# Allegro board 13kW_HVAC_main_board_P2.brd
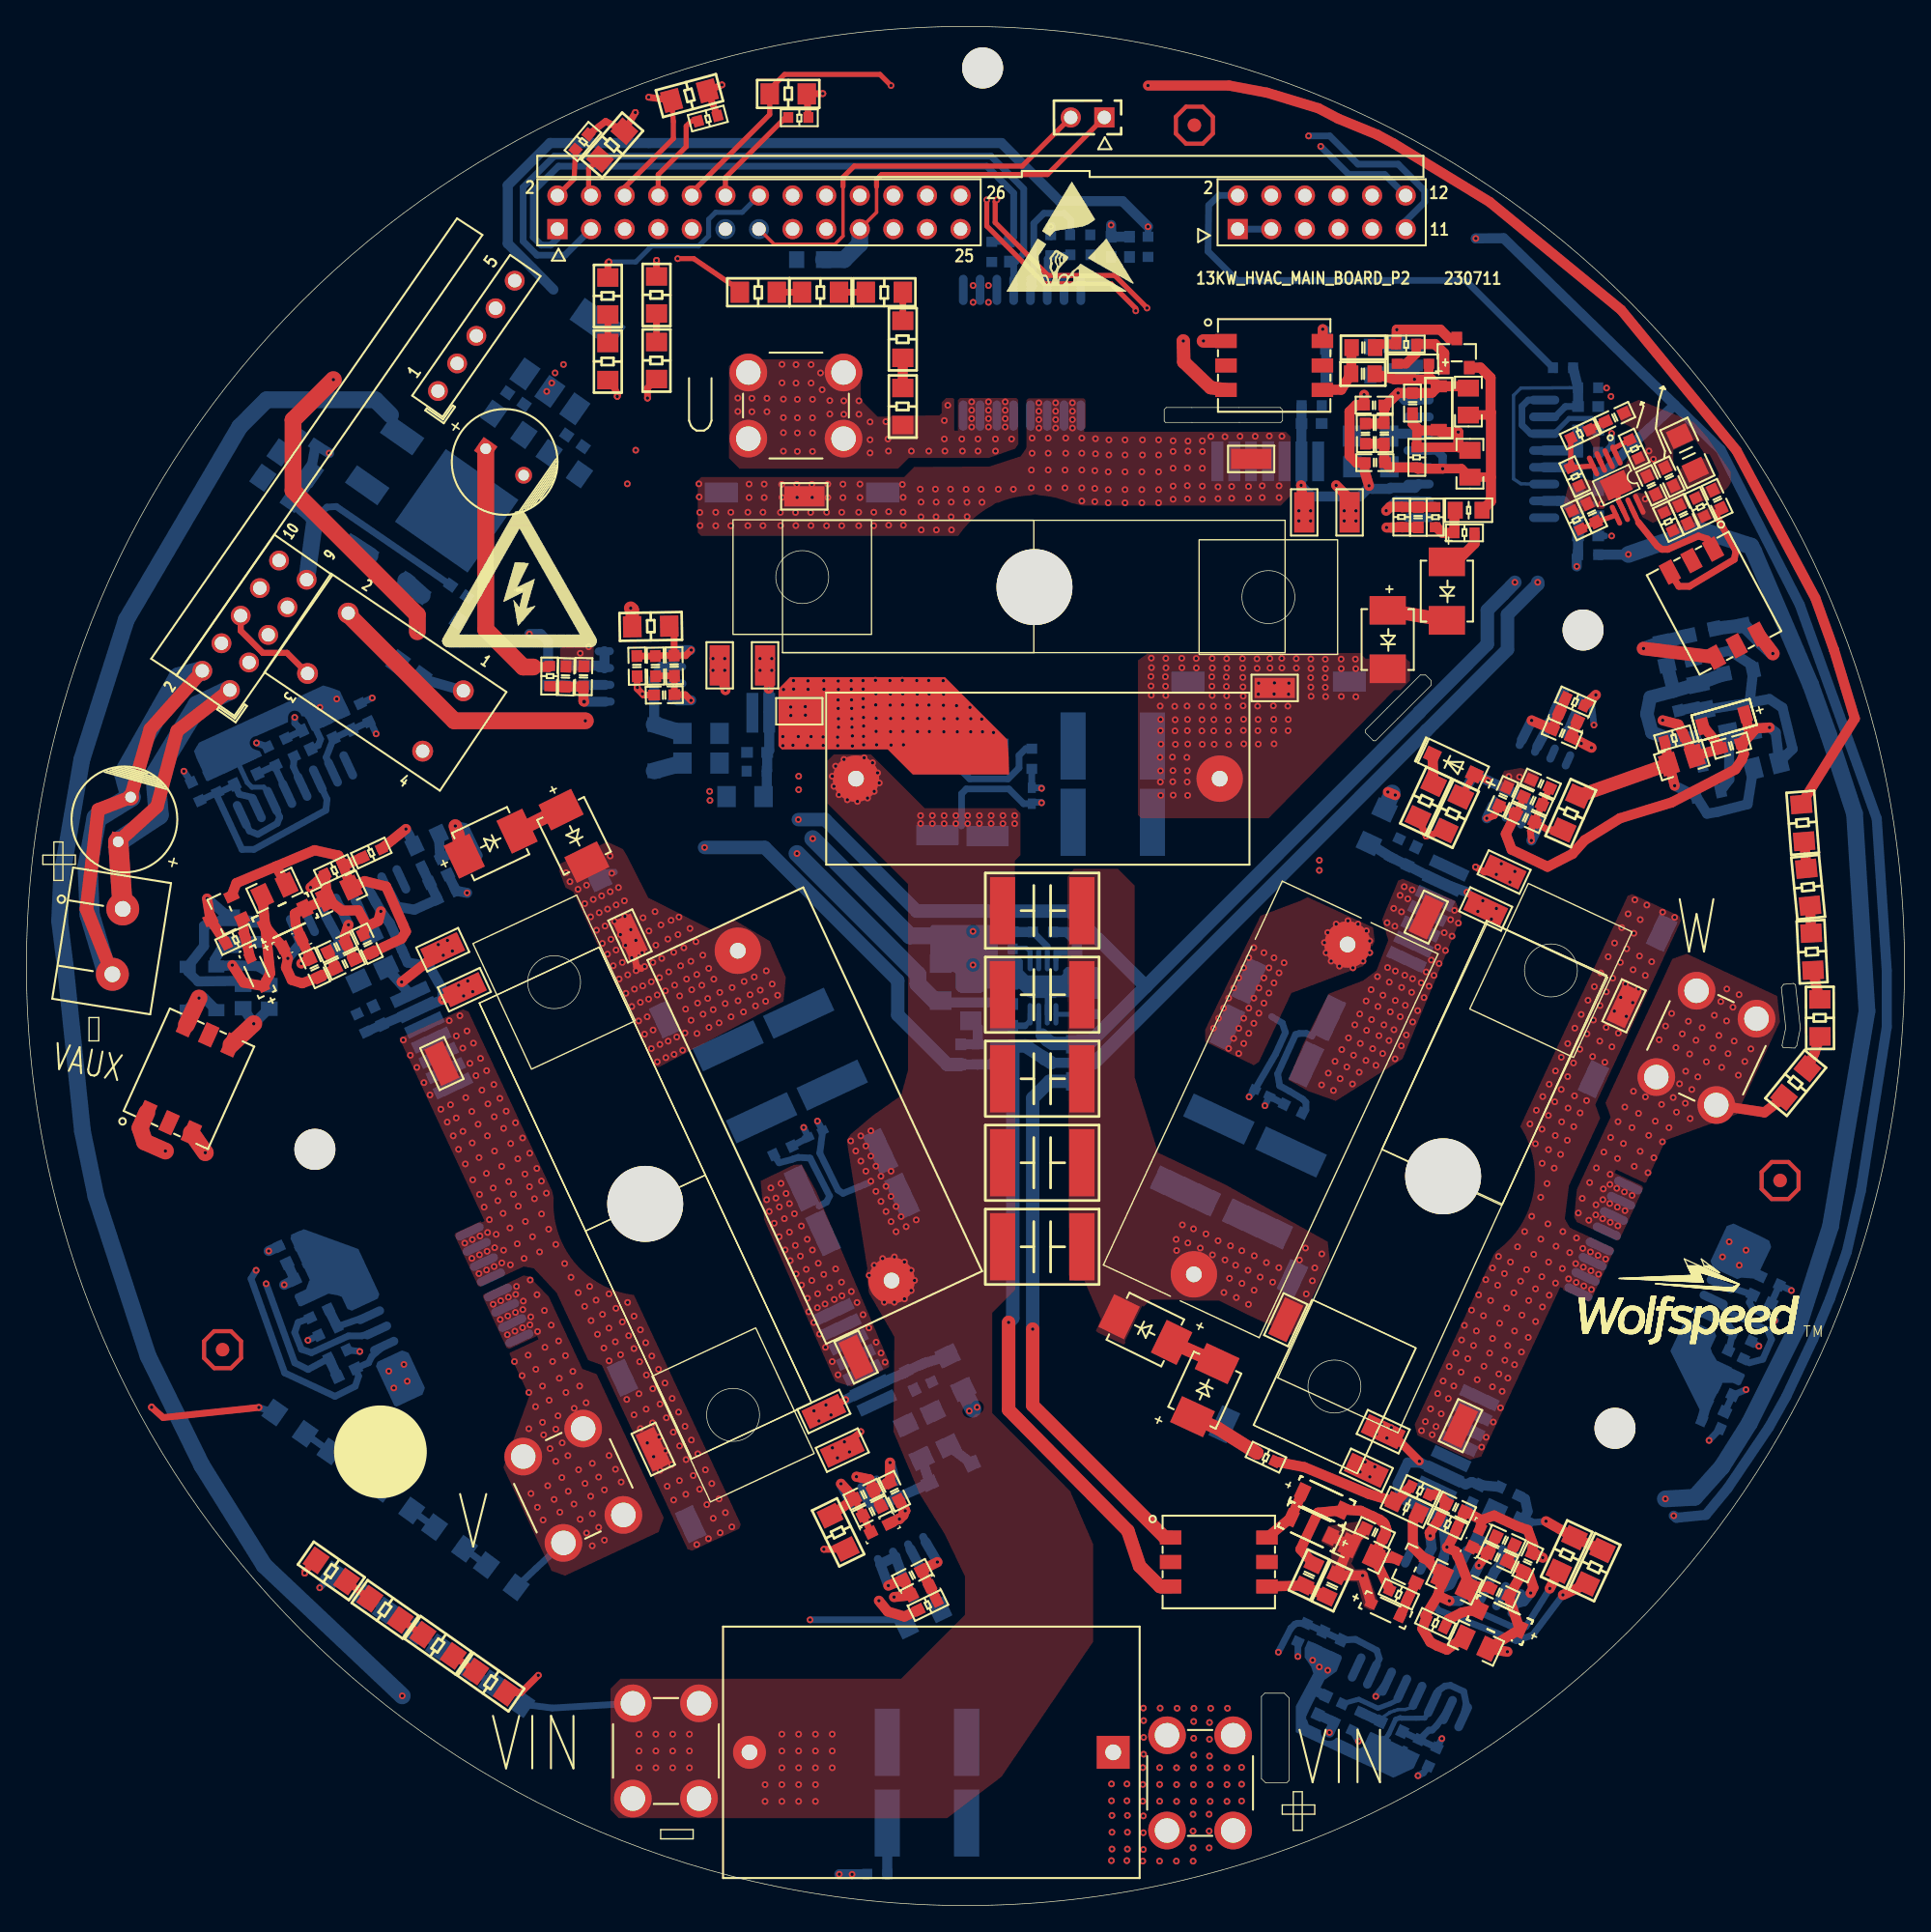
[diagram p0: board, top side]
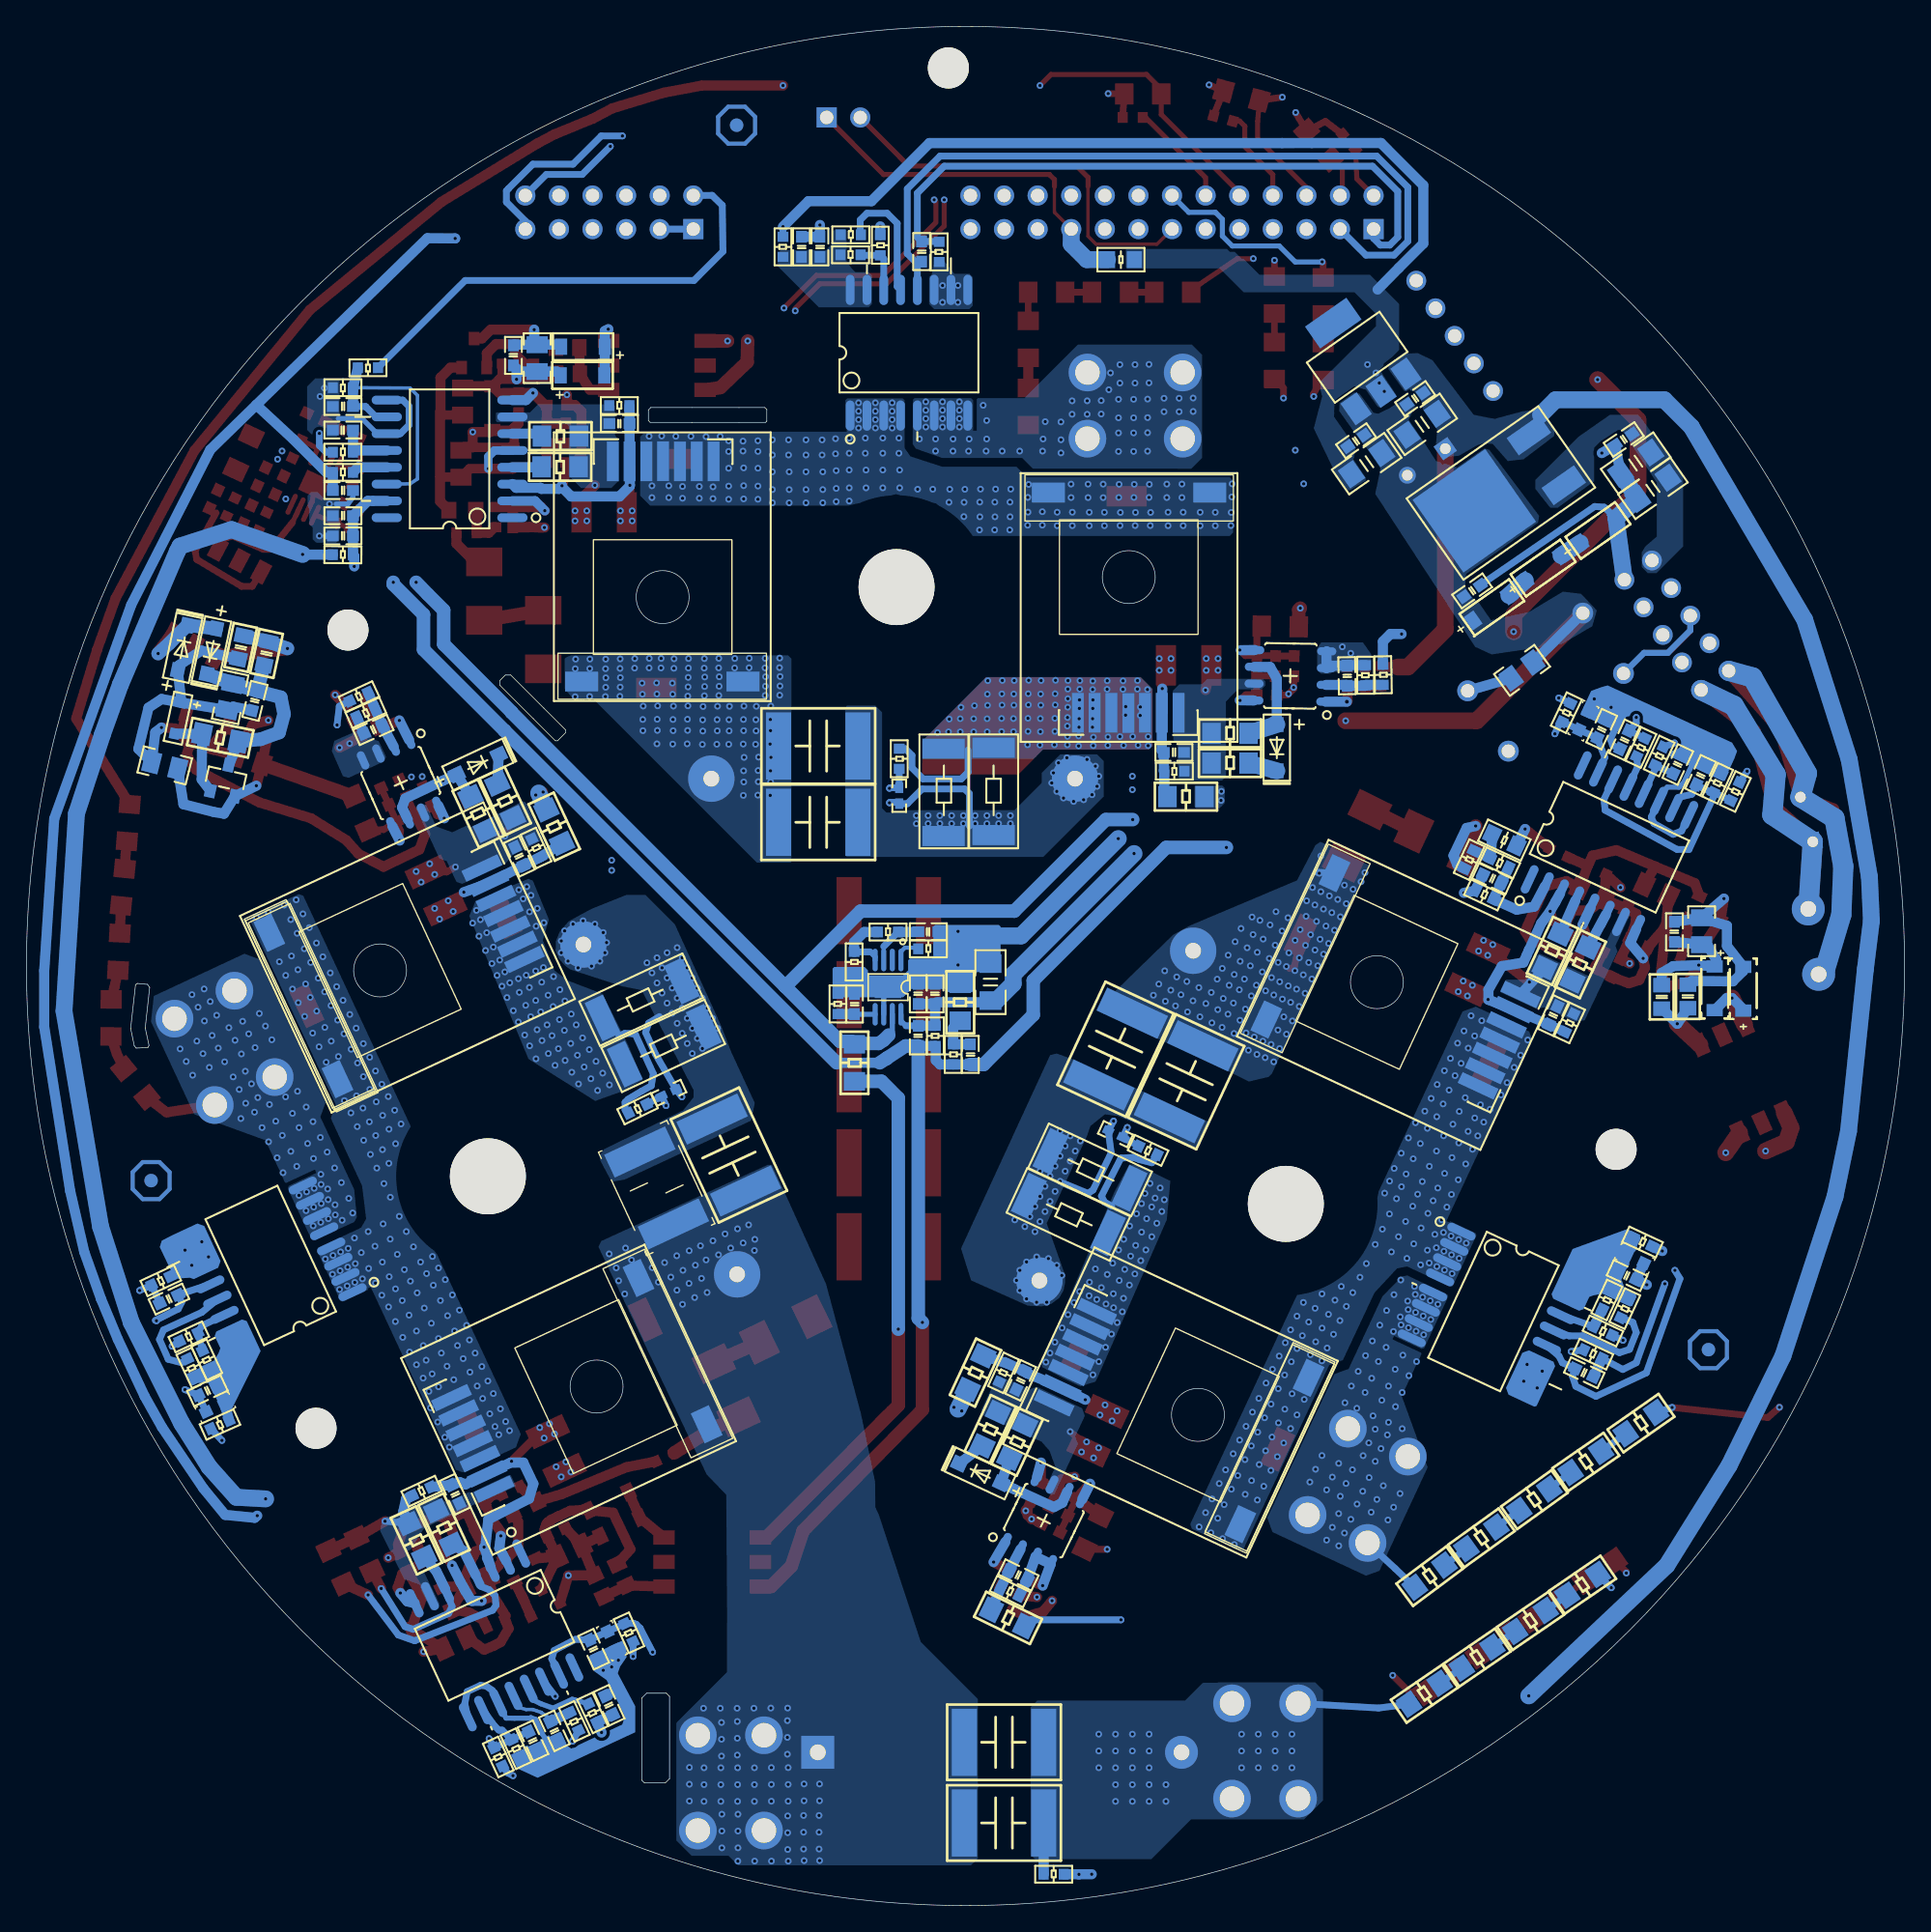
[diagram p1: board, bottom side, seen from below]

Outline 142 x 142 mm; copper layers: TOP, VCC02, GND03, PWM04, I_SAMPLING05, BOTTOM. Coordinates in mm from the lower left corner of the outline.
Outline path: circle c39.89,69.78 r2 ; circle c53.43,37.08 r2 ; circle c58.66,100.39 r2 ; circle c71,71 r71 ; circle c93.9,98.88 r2 ; circle c98.89,39.22 r2 ; circle c115.26,70.67 r2 ; 86.02,113.05 86.02,112.17 86.12,112.08 91.7,112.08 91.7,112.08 94.84,112.08 94.98,112.22 94.98,113.02 94.79,113.2 86.17,113.2 86.02,113.05 ; 93.38,15.8 93.38,9.59 93.7,9.27 95.28,9.27 95.47,9.46 95.47,15.68 95.1,16.05 93.62,16.05 93.38,15.8 ; 101.24,88.84 101.24,88.63 101.84,88.02 102.01,88.02 106.2,92.22 106.2,92.57 105.79,92.99 105.38,92.99 101.24,88.84 ; 132.69,69.38 132.85,69.61 133.61,69.68 133.75,69.59 134.12,66.29 133.85,64.98 133.7,64.8 132.82,64.84 132.74,65 133.02,66.32 132.69,69.38

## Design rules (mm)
net group 40MIL: nets IPH_U+ IPH_V+ IPH_W+

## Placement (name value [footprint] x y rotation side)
C1  1nF  [C0603]  97.16 112 180 bottom
C2  1nF  [C0603]  109.59 31.09 65 bottom
C3  1nF  [C0603]  26.56 67.26 295 bottom
C4  1nF  [C0603]  66.83 39.69 115 bottom
C5  1nF  [C0603]  104.74 79.29 245 bottom
C6  1nF  [C0603]  55.24 87.14 0 bottom
C7  5uF  [CAPFILM_31_5X18_5MM]  68.42 11.58 180 top
C8  2uF  [CAPFILM_31_5X12_5MM]  59.6 59.69 295 top
C9  2uF  [CAPFILM_31_5X12_5MM]  94.08 60.16 65 top
C10  2uF  [CAPFILM_31_5X12_5MM]  76.47 85.16 180 top
C11  0.22U  [C2220]  54.32 62.25 295 bottom
C12  0.22U  [C2220]  94.35 54.22 65 bottom
C13  0.22U  [C2220]  82.13 87.63 180 bottom
C14  NA  [0402]  59.66 58.3 25 bottom
C15  NA  [0402]  76.01 83.87 270 bottom
C16  NA  [0402]  93.43 61.42 155 bottom
C17  GRT21BR61H475KE13L  [C0603]  40.77 92.86 268 top
C18  0.1uF  [C0603]  42.13 92.87 269 top
C19  4.7uF  [C0603]  20.4 48.87 205 bottom
C20  4.7uF  [C0603]  83.4 125.34 90 bottom
C21  0.1uF  [C0603]  20.99 47.61 205 bottom
C22  0.1uF  [C0603]  82.01 125.34 90 bottom
C23  330pF  [C0603]  24.21 40.27 205 bottom
C24  330pF  [C0603]  74.32 124.99 90 bottom
C25  100pF  [C0603]  42.15 92.94 89 bottom
C26  1uF  [C0603]  46.16 93.66 271 top
C27  0.1uF  [C0603]  48.98 93.69 271 top
C28  2.2uF  [C0603]  47.56 93.66 271 top
C29  1uF  [C0603]  48.22 91.49 1 top
C30  100pF  [C0603]  118.07 113.28 0 bottom
C31  100pF  [C0603]  118.07 106.93 0 bottom
C32  4.7uF  [C0603]  127.73 37.63 335 bottom
C33  0.1uF  [C0603]  128.32 38.89 335 bottom
C34  GRT21BR61H475KE13L  [C0603]  67.62 23.79 26 top
C35  25V 220uF  [ECAP_D8P3_5]  7.41 82.08 74.5 top
C36  0.1uF  [C0603]  66.97 24.98 27 top
C37  1uF  [C0603]  101.95 109.04 180 top
C38  4.7uF  [C0603]  118.07 103.5 359.9 bottom
C39  330pF  [C0603]  131.23 45.83 335 bottom
C40  0.1uF  [C0603]  118.07 105.02 0 bottom
C41  25V 220uF  [ECAP_D8P3_5]  36.16 109.09 325 top
C42  10UF/25V  [C1206]  20.32 109 325 bottom
C43  2.2uF  [C0603]  102.66 111.24 90.3 top
C44  0.1uF  [C0603]  101.23 111.23 90.4 top
C45  1uF  [C0603]  101.9 113.39 0 top
C46  10UF/25V  [C1206]  19.02 107.09 325 bottom
C47  0.1uF  [C0603]  21.23 110.79 326 bottom
C48  100pF  [C0603]  67 24.98 206 bottom
C49  1uF  [C0603]  64.53 28.52 26 top
C50  0.1uF  [C0603]  63.31 31.07 26 top
C51  2.2uF  [C0603]  63.94 29.79 26 top
C52  1uF  [C0603]  65.63 31.31 116 top
C53  1uF  [C0603]  124.22 107.98 295 top
C54  47pF  [C0603]  105.23 104.91 270 top
C55  GRT21BR61H475KE13L  [C0603]  116.6 89.85 156 top
C56  0.1uF  [C0603]  116.1 88.58 157 top
C57  GRT21BR61H475KE13L  [0805_HV]  125.16 86.56 17.5 top
C58  3.3nF  [C0805]  123.85 94.62 102.2 bottom
C59  GRT21BR61H475KE13L  [0805_HV]  126.6 91.33 281.9 bottom
C60  1uF  [C0603]  125.3 105.12 295 top
C61  0.1uF  [C0603]  124.73 91.04 283.9 bottom
C62  GRT21BR61H475KE13L  [0805_HV]  131.55 86.16 14 bottom
C63  3.3nF  [C0805]  125.8 95.08 282 bottom
C64  10uF/35V  [C1206]  125.58 109.78 115 top
C65  1uF  [C0603]  120.1 112.46 25 top
C66  100pF  [C0603]  118.35 105.24 115 top
C67  GRT21BR61H475KE13L  [C0603]  128.89 87.65 15.8 top
C68  100pF  [C0603]  115.78 88.85 336 bottom
C69  1uF  [C0603]  127.83 106.28 115 top
C70  1uF  [C0603]  114.49 84.77 156 top
C71  0.1uF  [C0603]  113.32 82.2 156 top
C72  2.2uF  [C0603]  113.89 83.5 156 top
C73  1uF  [C0603]  111.65 83.82 246 top
C74  100pF  [C0603]  15.42 85.41 115 bottom
C75  100pF  [C0603]  21.17 88.1 115 bottom
C76  GRT21BR61H475KE13L  [0805_HV]  109.14 108.96 90 top
C77  3.3nF  [C0805]  101.08 117.73 180 top
C78  GRT21BR61H475KE13L  [0805_HV]  103.39 116.94 270 bottom
C79  1uF  [C0603]  25.77 72.69 115 top
C80  0.1uF  [C0603]  105.18 117.14 270 bottom
C81  GRT21BR61H475KE13L  [0805_HV]  109.02 113.65 90 top
C82  4.7uF  [C0603]  24.28 89.54 114.9 bottom
C83  3.3nF  [C0805]  101.05 115.75 0 top
C84  0.1uF  [C0603]  22.9 88.9 115 bottom
C85  0.1uF  [C0603]  24.08 71.13 205.4 top
C86  2.2uF  [C0603]  23.47 72.43 205.3 top
C87  GRT21BR61H475KE13L  [C0603]  104.8 113.54 90 top
C88  1uF  [C0603]  21.79 70.85 295 top
C89  100pF  [C0603]  103.7 12.45 245 bottom
C90  100pF  [C0603]  97.95 15.13 245 bottom
C91  1uF  [C0603]  73.3 68.89 270 bottom
C92  GRT21BR61H475KE13L  [0805_HV]  23.63 76.49 205 top
C93  3.3nF  [C0805]  16.38 68.7 270 bottom
C94  1uF  [C0603]  109.59 27.78 65 top
C95  GRT21BR61H475KE13L  [0805_HV]  15.35 73.63 270 bottom
C96  4.7uF  [C0603]  97.74 20.01 244.9 bottom
C97  0.1uF  [C0603]  17.4 73.58 270 bottom
C98  GRT21BR61H475KE13L  [0805_HV]  18.75 76.72 205 top
C99  0.1uF  [C0603]  99.12 19.37 245 bottom
C100  0.1uF  [C0603]  111.83 27.6 335.4 top
C101  2.2uF  [C0603]  111.23 26.31 335.3 top
C102  3.3nF  [C0805]  18.36 68.66 90 bottom
C103  47pF  [C0603]  31.17 77.6 25 bottom
C104  1uF  [C0603]  74.57 65.72 270 bottom
C105  GRT21BR61H475KE13L  [C0603]  20.09 72.73 205 top
C106  1uF  [C0603]  113.51 25.95 245 top
C107  10uF/35V  [C1206]  69.11 69.78 90 bottom
C108  100pF  [C0603]  79.4 68.13 90 bottom
C109  1uF  [C0603]  73.81 73.59 180 bottom
C110  1uF  [C0603]  70.63 64.32 90 bottom
C111  GRT21BR61H475KE13L  [0805_HV]  107.96 24.44 335 top
C112  3.3nF  [C0805]  96.97 24.99 245 top
C113  GRT21BR61H475KE13L  [0805_HV]  100.95 26.79 155 top
C114  0.1uF  [C0603]  101.94 28.19 155 top
C115  GRT21BR61H475KE13L  [0805_HV]  109.6 19.84 335 top
C116  3.3nF  [C0805]  98.71 24.15 65 top
C117  47pF  [C0603]  108.07 30.11 335 top
C118  GRT21BR61H475KE13L  [C0603]  111.38 23.67 335 top
C119  0.1uF  [C0603]  122.87 107.32 295 top
C120  0.1uF  [C0603]  74.57 68.89 270 bottom
C121  100pF  [C0603]  118.07 111.5 180 bottom
C122  100pF  [C0603]  17.14 86.22 295 bottom
C123  100pF  [C0603]  102.09 13.2 65 bottom
C124  10UF/25V  [C1206]  36.47 111.93 325 bottom
C125  10UF/25V  [C1206]  40.67 108.96 145 bottom
C126  0.1uF  [C0603]  41.47 110.69 145 bottom
C127  0.1uF  [C0603]  37 113.87 325 bottom
C128  GRT21BR61H475KE13L  [0805_HV]  28.92 93.34 144 bottom
C129  1uF  [C0603]  32.69 99.34 325 bottom
C130  0.47uF  [C2220]  76.8 56.13 180 top
C131  0.47uF  [C2220]  76.8 75.18 180 top
C133  0.22U  [C2220]  68.09 6.24 180 bottom
C134  0.22U  [C2220]  82.13 81.86 180 bottom
C135  0.47uF  [C2220]  76.8 68.83 180 top
C136  0.47uF  [C2220]  76.8 49.78 180 top
C137  0.47uF  [C2220]  76.8 62.48 180 top
C138  0.22U  [C2220]  88.89 56.71 65 bottom
C139  0.22U  [C2220]  59.65 64.71 295 bottom
C140  0.22U  [C2220]  68.09 12.34 180 bottom
CN1  -  [CON_5MM_2X1]  6.89 72.84 261 top
CN2  con_2mm54_5x2  [CON_2MM54_5X2]  17.24 96.75 55.2 top
CN3  con_2mm54_5x1  [CON_2MM54_5X1]  34.02 118.62 55.2 top
CON1  CON  [CON4_500X720-800X800]  88.74 9.27 0 top
CON2  CON  [CON4_500X720-800X800]  48.35 11.68 0 top
CON3  CON  [CON4_500X720-800X800]  41.35 31.72 25 top
CON4  CON  [CON4_500X720-800X800]  127.02 64.81 335 top
CON5  CON  [CON4_500X720-800X800]  58.18 113.35 270 top
D1  SL14PL-TP  [SOD-123]  107.88 86.22 155 bottom
D1_2  SL14PL-TP  [SOD-123]  107.89 86.21 155 top
D2  SL14PL-TP  [SOD-123]  69.89 32.66 25 bottom
D3  SL14PL-TP  [SOD-123]  47.46 87.5 270 bottom
D4  MURS160T3G  [SMB]  107.39 99.33 90 top
D5  MURS160T3G  [SMB]  102.92 95.67 90 top
D6  PMEG6010CEGWJ  [SOD-123]  128.01 94.78 282 bottom
D7  18.51V  [SOD323F]  130.54 89.73 282.2 bottom
D8  PMEG6010CEGWJ  [SOD-123]  130.19 95.04 102 bottom
D9  3V  [SMDSOD123]  128.36 89.58 15.8 top
D10  PMEG6010CEGWJ  [SMDSOD123]  99.92 117.8 180 bottom
D11  18.51V  [SOD323F]  104.83 116.51 180 top
D12  PMEG6010CEGWJ  [SMDSOD123]  99.96 115.63 0 bottom
D13  3V  [SMDSOD123]  106.78 113.16 90 top
D14  MURS160T3G  [SMB]  35.1 80.25 205.3 top
D15  MURS160T3G  [SMB]  41.4 80.83 116.2 top
D16  PMEG6010CEGWJ  [SMDSOD123]  12.19 69.28 270 bottom
D17  18.51V  [SOD323F]  17.41 70.57 115 top
D18  PMEG6010CEGWJ  [SMDSOD123]  14.36 69.31 90 bottom
D19  3V  [SMDSOD123]  19.56 74.65 205 top
D20  MURS160T3G  [SMB]  89.09 38.95 245.1 top
D21  MURS160T3G  [SMB]  84.6 43.53 334 top
D22  PMEG6010CEGWJ  [SMDSOD123]  97.99 30.57 155 top
D23  18.51V  [SOD323F]  102.76 22.34 335 top
D24  PMEG6010CEGWJ  [SMDSOD123]  97.12 28.61 335 top
D25  3V  [SMDSOD123]  111.41 21.58 335 top
D26  5.6V  [SMDSOD123]  23.17 103.91 325 bottom
D27  5.6V  [SMDSOD123]  27.32 101.07 325 bottom
D28  5.6V  [SMDSOD123]  31.27 98.06 325 bottom
J1  2*13P  [HDR2X13H-254MM-F]  55.39 127.96 0 top
J2  2*6P  [HDR2X6H-254MM-F]  97.93 127.96 0 top
L1  -  [L4_550X1050-900X1600]  27.14 92.45 236 top
NOREF  -  []  0.05 73.73 0 top
NOREF#2  -  []  26.76 34.29 0 top
NOREF#3  #VAL  [unnamed#2]  14.83 42.01 0 top
NOREF#4  #VAL  [unnamed#2]  88.31 134.54 0 top
NOREF#5  #VAL  [unnamed#2]  132.59 54.79 0 top
NOREF#6  -  []  37.26 99.37 0 top
NOREF#7  -  []  79.02 125.19 0 top
NOREF#8  -  []  134.9 48.27 0 top
NOREF#9  #VAL  [unnamed#2]  14.83 42.01 180 bottom
NOREF#10  #VAL  [unnamed#3]  107.11 55.11 65 bottom
NOREF#11  #VAL  [unnamed#3]  46.78 53.02 295 bottom
NOREF#12  #VAL  [unnamed#2]  132.57 54.78 180 bottom
NOREF#13  #VAL  [unnamed#2]  88.31 134.54 180 bottom
NOREF#14  #VAL  [unnamed#3]  76.21 99.63 180 bottom
NTC1  NTCALUG02A103F161  [NTC2_54]  80.23 135.12 180.1 top
PAD1  PAD  [TEST_270X100_SMT]  94.38 92.01 0 top
PAD2  PAD  [TEST_270X100_SMT]  95.21 44.27 65 top
PAD3  PAD  [TEST_270X100_SMT]  45.63 73.27 295 top
PAD4  PAD  [TEST_270X100_SMT]  100.04 105.28 90 top
PAD5  PAD  [TEST_270X100_SMT]  101.31 32.89 335 top
PAD6  PAD  [TEST_270X100_SMT]  31.47 72.23 205 top
PAD7  PAD  [TEST_270X100_SMT]  33.11 69.21 25 top
PAD8  PAD  [TEST_270X100_SMT]  31.41 63.63 115 top
PAD9  PAD  [TEST_270X100_SMT]  102.58 35.81 335 top
PAD10  PAD  [TEST_270X100_SMT]  108.42 36.27 65 top
PAD11  PAD  [TEST_270X100_SMT]  92.6 109.32 0 top
PAD12  PAD  [TEST_270X100_SMT]  96.61 105.28 90 top
PAD13  PAD  [TEST_270X100_SMT]  47.4 34.48 295 top
PAD14  PAD  [TEST_270X100_SMT]  120.79 67.99 65 top
PAD15  PAD  [TEST_270X100_SMT]  58.82 106.49 0 top
PAD16  PAD  [TEST_270X100_SMT]  111.72 78.1 335 top
PAD17  PAD  [TEST_270X100_SMT]  61.69 34.41 25 top
PAD18  PAD  [TEST_270X100_SMT]  52.42 93.72 270 top
PAD19  PAD  [TEST_270X100_SMT]  60.29 37.33 25 top
PAD20  PAD  [TEST_270X100_SMT]  110.33 75.31 335 top
PAD21  PAD  [TEST_270X100_SMT]  105.83 74.7 65 top
PAD22  PAD  [TEST_270X100_SMT]  55.84 93.72 90 top
PAD23  PAD  [TEST_270X100_SMT]  58.43 90.25 0 top
PAD24  PAD  [TEST_270X100_SMT]  62.73 41.45 295 top
PAD_A1  PAD  [NTH122]  72.29 138.86 0 top
PAD_A2  PAD  [NTH122]  21.81 57.15 0 top
PAD_A3  PAD  [NTH122]  117.69 96.39 0 top
PAD_A4  PAD  [NTH122]  120.11 36.06 0 top
Q1  E3M0075120U1  [T2PAK_7L]  93.87 109.16 0 bottom
Q2  E3M0075120U1  [T2PAK_7L]  30.6 65.39 115 bottom
Q3  E3M0075120U1  [T2PAK_7L]  108.27 34.9 245 bottom
Q4  E3M0075120U1  [T2PAK_7L]  105.93 74.97 65 bottom
Q5  E3M0075120U1  [T2PAK_7L]  62.72 41.44 295 bottom
Q6  E3M0075120U1  [T2PAK_7L]  58.69 90.11 180 bottom
Q7  SOT23-3  [SOT-23-BCE]  126.93 85.11 192.5 bottom
Q8  SOT23-3  [SOT-23-BCE]  108.14 117.32 0 top
Q9  SOT23-3  [SOT-23-BCE]  14.91 74.97 115 top
Q10  SOT23-3  [SOT-23-BCE]  104.48 25.76 65 top
R1  620K  [R1206]  35.12 16.88 325 top
R2  620K  [R1206]  36.3 16.01 325.6 bottom
R3  330K  [R1206]  66.26 113.28 270 top
R4  330K  [R1206]  35.91 24.89 323.3 bottom
R5  330K  [R1206]  133.77 62.16 230.8 top
R6  10K  [R0603]  112.11 31.31 155 bottom
R7  10K  [R0603]  25.33 66.7 295 bottom
R8  10K  [R0603]  97.17 113.35 180 bottom
R9  620K  [R1206]  31.13 19.66 325 top
R10  620K  [R1206]  32.31 18.74 325.6 bottom
R11  330K  [R1206]  66.26 118.36 270 top
R12  330K  [R1206]  31.99 27.78 324.3 bottom
R13  330K  [R1206]  135.6 67.08 270.3 top
R14  620K  [R1206]  27.12 22.38 325 top
R15  620K  [R1206]  28.28 21.51 325.6 bottom
R16  330K  [R1206]  64.86 121.92 0 top
R17  330K  [R1206]  27.99 30.67 324.3 bottom
R18  330K  [R1206]  135.01 72.08 272.8 top
R19  620K  [R1206]  23.05 25.29 325.1 top
R20  620K  [R1206]  24.34 24.24 325.6 bottom
R21  330K  [R1206]  60.04 121.92 0 top
R22  330K  [R1206]  134.71 76.96 275.7 top
R23  330K  [R1206]  24.09 33.52 325.3 bottom
R24  NA  [R1206]  105.8 83.48 245 bottom
R24_2  NA  [R1206]  105.81 83.46 245 top
R25  NA  [R1206]  69.12 36 115 bottom
R26  NA  [R1206]  51 86.34 0 bottom
R27  22  [R1206]  107.84 82.53 245 bottom
R27_2  22  [R1206]  107.87 82.5 245 top
R28  22  [R1206]  67.09 35.05 115 bottom
R29  22  [R1206]  51 88.58 0 bottom
R30  10K  [R0603]  103.47 79.92 245 bottom
R31  10K  [R0603]  68.13 40.26 115 bottom
R32  620K  [R1206]  47.64 116.75 270 top
R33  620K  [R1206]  43.96 116.68 270 top
R34  10K  [R0603]  55.21 85.72 0 bottom
R35  0R  [R0603]  64.33 2.37 180 bottom
R36  0R  [R0603]  72.99 124.96 90 bottom
R37  0R  [R0603]  23.56 41.67 205 bottom
R38  NA  [R1206]  44.29 133.03 229 top
R39  NA  [R1206]  50.13 136.77 195 top
R40  NA  [R1206]  57.6 136.9 180 top
R41  0R  [R0603]  57.19 57.07 25 bottom
R42  0R  [R0603]  76.01 86.66 270 bottom
R43  620K  [R1206]  47.64 121.71 270 top
R44  620K  [R1206]  43.96 121.63 270 top
R45  330K  [R1206]  55.34 121.92 0 top
R46  330K  [R1206]  19.93 36.46 325.1 bottom
R47  330K  [R1206]  134.3 81.82 274.4 top
R48  0.002R  [R2512]  63.22 52.22 25 bottom
R49  0.002R  [R2512]  61.58 55.6 25 bottom
R50  0.002R  [R2512]  68.87 84.2 270 bottom
R51  0R  [R0603]  51.52 135.05 195 top
R52  0.002R  [R2512]  93.78 64.98 155 bottom
R53  0.002R  [R2512]  95.44 68.47 155 bottom
R54  1R  [R1206]  102.1 81.53 245 bottom
R55  1R  [R1206]  70.24 40.27 115 bottom
R56  1R  [R1206]  54.33 83.8 0 bottom
R57  0R  [R0603]  26.15 79.55 25 top
R58  0R  [R0603]  19.81 50.14 205 bottom
R59  0R  [R0603]  84.8 125.34 90 bottom
R60  33K  [R0603]  22.51 45.76 295 bottom
R61  10K  [R0603]  22.8 43.42 25 bottom
R62  33K  [R0603]  79.69 124.74 180 bottom
R63  10K  [R0603]  77.44 125.47 270 bottom
R64  10K  [R0603]  21.15 45.11 295 bottom
R65  10K  [R0603]  79.67 126.25 180 bottom
R66  10R  [R0603]  39.56 92.91 269.9 top
R67  100R  [R0603]  39.43 93.01 269 bottom
R68  1R  [R1206]  47.2 96.66 181 top
R69  4.7K  [R0603]  40.75 92.97 90 bottom
R70  4.9K  [R0603]  118.07 109.83 180 bottom
R71  22  [R1206]  101.62 111.04 180 bottom
R72  100R  [R0603]  116.18 116.21 359.8 bottom
R73  0R  [R0603]  127.37 36.35 336 bottom
R74  22  [R1206]  101.65 108.72 180 bottom
R75  4.7K  [R0603]  118.07 114.7 0 bottom
R76  33K  [R0603]  128.37 41.24 65 bottom
R77  10K  [R0603]  129.72 42.97 155 bottom
R78  10K  [R0603]  129.49 40.62 65 bottom
R79  NA  [R0805]  59.25 124.38 180 bottom
R80  100R  [R0603]  118.07 108.3 180 bottom
R81  10R  [R0603]  118.07 102.08 180.5 bottom
R83  10R  [R0603]  68.16 22.69 26 top
R84  0R  [R0603]  58.36 135.12 180 top
R85  0R  [R0603]  95.79 60.21 334 bottom
R86  100R  [R1206]  67.78 21.74 26 bottom
R88  0R  [R0603]  42.01 133.26 230 top
R89  1R  [R1206]  61.37 28.2 296 top
R90  4.7K  [R0603]  67.63 23.72 206 bottom
R93  3K  [R0805]  109.04 105.44 180 top
R94  4.7K  [R0603]  106.51 104.92 270 top
R95  680R  [R0603]  103.99 104.93 90 top
R96  2.7K  [R0603]  124.59 88.19 15.8 top
R97  100k  [R0603]  124.15 104.59 115 top
R98  1k  [R1206]  127.35 88.25 191.5 bottom
R99  10R  [R0603]  117.09 90.97 156 top
R100  3.24K  [R0603]  117.46 111.2 25 top
R101  100R  [R0603]  116.86 91.35 155 bottom
R102  1R  [R1206]  116.76 82.56 66 top
R103  4.7K  [R0603]  116.34 90.14 336 bottom
R104  NA  [R0603]  121.56 110.07 295 top
R105  97.6K  [R0603]  117.2 104.7 115 top
R106  11K  [R0603]  117.07 107.98 295 top
R107  100k  [R0603]  126.54 105.68 295 top
R108  4.9K  [R0603]  18.55 86.87 295 bottom
R109  22  [R1206]  24.52 71.14 295 bottom
R110  100R  [R0603]  12.79 84.19 295 bottom
R111  22  [R1206]  26.61 72.14 295 bottom
R112  4.7K  [R0603]  14.13 84.81 115 bottom
R113  2.7K  [R0603]  105.12 109.44 90 top
R114  100R  [R0603]  19.93 87.52 295 bottom
R115  1K  [R0603]  104.32 118 180 top
R116  10R  [R0603]  25.57 90.15 295.5 bottom
R117  4.9K  [R0603]  100.57 13.91 65 bottom
R118  22  [R1206]  112.51 27.59 65 bottom
R118_2  22  [R1206]  116.45 26.53 65 top
R119  100R  [R0603]  106.33 11.23 65 bottom
R120  22  [R1206]  110.43 28.57 65 bottom
R120_2  22  [R1206]  118.57 25.57 65 top
R121  4.7K  [R0603]  104.99 11.85 245 bottom
R122  3K  [R0805]  30.26 80.51 25 bottom
R123  100R  [R0603]  99.19 14.55 65 bottom
R124  4.7K  [R0603]  30.6 78.8 25 bottom
R125  2.7K  [R0603]  23.27 78.25 205 top
R126  1K  [R0603]  15.81 73 205 top
R127  10R  [R0603]  96.45 20.61 65.5 bottom
R128  100k  [R0603]  73.28 65.72 90 bottom
R129  3.24K  [R0603]  76.86 73.57 180 bottom
R130  680R  [R0603]  31.78 76.37 205 bottom
R131  97.6K  [R0603]  80.64 68.13 90 bottom
R132  NA  [R0603]  73.81 72.3 180 bottom
R133  11K  [R0603]  79.42 71.31 270 bottom
R134  100k  [R0603]  71.93 64.32 270 bottom
R135  3k  [R0805]  104.36 30.09 155 top
R136  4.7K  [R0603]  105.37 31.36 155 top
R137  2.7K  [R0603]  106.52 21.32 335 top
R138  1K  [R0603]  103.76 23.53 155 top
R139  680R  [R0603]  107.47 28.83 155 top
R140  0R  [R0603]  108.73 103.73 0 top
R141  0R  [R0603]  32.92 79.04 295 bottom
R142  0R  [R0603]  93.72 33.88 155 top
R143  0R  [R0603]  131.84 47.22 335 bottom
R2512  0.002R  [R2512]  72.66 84.12 270 bottom
RJ0  0R  [R1206]  79.4 63.69 90 bottom
RJ1  0R  [R1206]  71.4 68.26 270 bottom
T1  Trans  [T4_700X850X600]  127.6 98.42 298 top
T2  Trans  [T4_700X850X600]  94.34 116.38 0 top
T3  Trans  [T4_700X850X600]  12.28 62.48 65.7 top
T4  Trans  [T4_700X850X600]  90.15 25.96 0 top
U1  ACS733KLATR-40AB-T  [SOP16_127-1063X1050]  31.08 44.89 205 bottom
U2  UCC5350MCDR  [SOIC-8]  46.44 92.92 1 bottom
U3  ACS733KLATR-40AB-T  [SOP16_127-1063X1050]  75.28 117.34 90 bottom
U4  UCC21710QDWQ1  [FP-DW0016B-IPC_B]  110.01 109.32 0 bottom
U5  ACS733KLATR-40AB-T  [SOP16_127-1063X1050]  123.53 48.37 335 bottom
U6  LF50ABDT-TR  [TO252AB]  32.95 105.11 55 bottom
U7  UCC5350MCDR  [SOIC-8]  65.08 29.09 116 bottom
U8  UCC25800-Q1  [SOP8_065-505X310-HS185X215]  120.2 107.34 295 top
U9  UCC5350MCDR  [SOIC-8]  113.7 84.82 246 bottom
U10  UCC21710QDWQ1  [FP-DW0016B-IPC_B]  22.31 79.98 115 bottom
U11  UCC21710QDWQ1  [FP-DW0016B-IPC_B]  106.61 20.42 245 bottom
U12  UCC25800-Q1  [SOP8_065-505X310-HS185X215]  76.86 69.4 270 bottom
U13  AZ1117IH-3.3  [SOT223]  41.38 117 145 bottom

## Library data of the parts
C1-C6 C17-C34 C36-C40 C43-C45 C47-C56 C60 C61 C65-C75 C79 C80 C82 C84-C91 C94 C96 C97 C99-C101 C103-C106 C108-C110 C114 C117-C123 C126 C127 C129 = C0603
C7 = CAPFILM_31_5X18_5MM: User Part Number: HAMP; Tolerance: #TOL
C8-C10 = CAPFILM_31_5X12_5MM: Tolerance: #TOL; User Part Number: HAMP
C11-C13 C130 C131 C133-C140 = C2220: User Part Number: HAMP; Tolerance: #TOL
C14-C16 = 0402: Tolerance: #TOL; User Part Number: HAMP
C35 C41 = ECAP_D8P3_5: User Part Number: HAMP; Tolerance: #TOL
C42 C46 C64 C107 C124 C125 = C1206
C57 C59 C62 C76 C78 C81 C92 C95 C98 C111 C113 C115 C128 = 0805_HV: User Part Number: HAMP; Tolerance: #TOL
C58 C63 C77 C83 C93 C102 C112 C116 = C0805: Tolerance: #TOL; User Part Number: HAMP
CN1 = CON_5MM_2X1: User Part Number: HAMP; Tolerance: #TOL
CN2 = CON_2MM54_5X2: User Part Number: HAMP; Tolerance: #TOL
CN3 = CON_2MM54_5X1: Tolerance: #TOL; User Part Number: HAMP
CON1-CON5 = CON4_500X720-800X800: Tolerance: #TOL; User Part Number: HAMP
D1 D1_2 D2 D3 D6 D8 = SOD-123: Tolerance: #TOL; User Part Number: HAMP
D4 D5 D14 D15 D20 D21 = SMB: Tolerance: #TOL; User Part Number: HAMP
D7 D11 D17 D23 = SOD323F: Tolerance: #TOL; User Part Number: HAMP
D9 D10 D12 D13 D16 D18 D19 D22 D24-D28 = SMDSOD123: Tolerance: #TOL; User Part Number: HAMP
J1 = HDR2X13H-254MM-F: Tolerance: #TOL; User Part Number: HAMP
J2 = HDR2X6H-254MM-F: Tolerance: #TOL; User Part Number: HAMP
L1 = L4_550X1050-900X1600: Tolerance: #TOL; User Part Number: HAMP
NOREF#3 NOREF#4 NOREF#9-NOREF#11 NOREF#13 = -: User Part Number: HAMP; Tolerance: #TOL
NOREF#5 NOREF#12 NOREF#14 = -: Tolerance: #TOL; User Part Number: HAMP
NTC1 = NTC2_54: Tolerance: #TOL; User Part Number: HAMP
PAD1-PAD24 = TEST_270X100_SMT: Tolerance: #TOL; User Part Number: HAMP
PAD_A1-PAD_A4 = NTH122: Tolerance: #TOL; User Part Number: HAMP
Q1-Q6 = T2PAK_7L: User Part Number: HAMP; Tolerance: #TOL
Q7-Q10 = SOT-23-BCE: Tolerance: #TOL; User Part Number: HAMP
R1-R5 R9-R24 R24_2 R25-R27 R27_2 R28 R29 R32 R33 R38-R40 R43-R47 R54-R56 R68 R71 R74 R86 R89 R98 R102 R109 R111 R118 R118_2 R120 R120_2 RJ0 RJ1 = R1206: Tolerance: #TOL; User Part Number: HAMP
R6-R8 R30 R31 R34-R37 R41 R42 R51 R57-R67 R69 R70 R72 R73 R75-R78 R80 R81 R83-R85 R88 R90 R94-R97 R99-R101 R103-R108 R110 R112-R117 R119 R121 R123-R134 R136-R143 = R0603
R48-R50 R52 R53 R2512 = R2512: User Part Number: HAMP; Tolerance: #TOL
R79 R93 R122 R135 = R0805: Tolerance: #TOL; User Part Number: HAMP
T1-T4 = T4_700X850X600: Tolerance: #TOL; User Part Number: HAMP
U1 U3 U5 = SOP16_127-1063X1050: User Part Number: HAMP; Tolerance: #TOL
U2 U7 U9 = SOIC-8: Tolerance: #TOL; User Part Number: HAMP
U4 U10 U11 = FP-DW0016B-IPC_B: User Part Number: HAMP; Tolerance: #TOL
U6 = TO252AB: Tolerance: #TOL; User Part Number: HAMP
U8 U12 = SOP8_065-505X310-HS185X215: Tolerance: #TOL; User Part Number: HAMP
U13 = SOT223: Tolerance: #TOL; User Part Number: HAMP

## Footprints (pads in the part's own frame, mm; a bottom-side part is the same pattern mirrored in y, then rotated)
0402
  rect 0.787x0.61 smd: 1(-0.6,0) 2(0.6,0)
0805_HV
  rect 1.27x1.6 smd: 1(-1.016,0) 2(1.016,0)
C0603
  rect 0.889x0.813 smd: 1(-0.762,0) 2(0.762,0)
C0805
  rect 1.092x1.27 smd: 1(-0.89,0) 2(0.89,0)
C1206
  rect 1.397x1.651 smd: 1(-1.397,0) 2(1.397,0)
C2220
  rect 1.905x5.08 smd: 1(-3,0) 2(3,0)
CAPFILM_31_5X12_5MM
  round 3.505 hole 1.194: 1(-13.75,0) 2(13.75,0)
CAPFILM_31_5X18_5MM
  rect 2.489x2.489 hole 1.194: 1(-13.75,0)
  round 2.489 hole 1.194: 2(13.75,0)
CON4_500X720-800X800
  round 2.845 hole 1.854: 1(-2.5,3.6) 2(2.5,3.6) 3(-2.5,-3.6) 4(2.5,-3.6)
CON_2MM54_5X1
  round 1.499 hole 1.016: 1(-5.08,0) 2(-2.54,0) 3(0,0) 4(2.54,0) 5(5.08,0)
CON_2MM54_5X2
  round 1.499 hole 1.016: 1(-5.08,-1.27) 2(-5.08,1.27) 3(-2.54,-1.27) 4(-2.54,1.27) 5(0,-1.27) 6(0,1.27) 7(2.54,-1.27) 8(2.54,1.27) 9(5.08,-1.27) 10(5.08,1.27)
CON_5MM_2X1
  round 2.489 hole 1.194: 1(-2.5,0) 2(2.5,0)
ECAP_D8P3_5
  rect 1.27x1.27 hole 0.813: 1(-1.75,0)
  round 1.27 hole 0.813: 2(1.75,0)
FP-DW0016B-IPC_B
  oval 2.286x0.66 smd: 1(-4.75,4.445) 2(-4.75,3.175) 3(-4.75,1.905) 4(-4.75,0.635) 5(-4.75,-0.635) 6(-4.75,-1.905) 7(-4.75,-3.175) 8(-4.75,-4.445) 9(4.75,-4.445) 10(4.75,-3.175) 11(4.75,-1.905) 12(4.75,-0.635) 13(4.75,0.635) 14(4.75,1.905) 15(4.75,3.175) 16(4.75,4.445)
HDR2X6H-254MM-F
  rect 1.524x1.524 hole 1.016: 1(-6.35,-1.27)
  round 1.524 hole 1.016: 2(-6.35,1.27) 3(-3.81,-1.27) 4(-3.81,1.27) 5(-1.27,-1.27) 6(-1.27,1.27) 7(1.27,-1.27) 8(1.27,1.27) 9(3.81,-1.27) 10(3.81,1.27) 11(6.35,-1.27) 12(6.35,1.27)
HDR2X13H-254MM-F
  rect 1.524x1.524 hole 1.016: 1(-15.24,-1.27)
  round 1.524 hole 1.016: 2(-15.24,1.27) 3(-12.7,-1.27) 4(-12.7,1.27) 5(-10.16,-1.27) 6(-10.16,1.27) 7(-7.62,-1.27) 8(-7.62,1.27) 9(-5.08,-1.27) 10(-5.08,1.27) 12(-2.54,1.27) 14(0,1.27) 15(2.54,-1.27) 16(2.54,1.27) 17(5.08,-1.27) 18(5.08,1.27) 19(7.62,-1.27) 20(7.62,1.27) 21(10.16,-1.27) 22(10.16,1.27) 23(12.7,-1.27) 24(12.7,1.27) 25(15.24,-1.27) 26(15.24,1.27)
  round 1.016 hole 1.016: 11(-2.54,-1.27) 13(0,-1.27)
L4_550X1050-900X1600
  round 1.575 hole 1.016: 1(-2.75,5.25) 2(-2.75,-5.25) 3(2.75,-5.25) 4(2.75,5.25)
NTC2_54
  rect 1.524x1.524 hole 1.016: 1(-1.27,0)
  round 1.524 hole 1.016: 2(1.27,0)
NTH122
  round 3.099 hole 3.099 unplated: (0,0)
R0603
  rect 0.762x0.813 smd: 1(-0.762,0) 2(0.762,0)
R0805
  rect 1.143x1.27 smd: 1(-1.016,0) 2(1.016,0)
R1206
  rect 1.397x1.6 smd: 1(-1.4,0) 2(1.4,0)
R2512
  rect 1.524x3.2 smd: 1(-3.3,0) 2(3.3,0)
SMB
  rect 2.159x2.743 smd: 1(2.21,0) 2(-2.21,0)
SMDSOD123
  rect 0.914x1.219 smd: 1(1.651,0) 2(-1.651,0)
SOD323F
  rect 0.813x0.762 smd: 1(-1.2,0) 2(1.2,0)
SOD-123
  rect 1.118x1.016 smd: 1(-1.75,0) 2(1.75,0)
SOIC-8
  oval 1.448x0.61 smd: 1(-2.725,1.905) 2(-2.725,0.635) 3(-2.725,-0.635) 4(-2.725,-1.905) 5(2.725,-1.905) 6(2.725,-0.635) 7(2.725,0.635) 8(2.725,1.905)
SOP8_065-505X310-HS185X215
  oval 1.702x0.381 smd: 1(-2.05,0.975) 2(-2.05,0.325) 3(-2.05,-0.325) 4(-2.05,-0.975) 5(2.05,-0.975) 6(2.05,-0.325) 7(2.05,0.325) 8(2.05,0.975)
  rect 1.651x2.007 smd: 9(0,0)
SOP16_127-1063X1050
  oval 2.286x0.66 smd: 1(-4.75,4.445) 2(-4.75,3.175) 3(-4.75,1.905) 4(-4.75,0.635) 5(-4.75,-0.635) 6(-4.75,-1.905) 7(-4.75,-3.175) 8(-4.75,-4.445) 9(4.75,-4.445) 10(4.75,-3.175) 11(4.75,-1.905) 12(4.75,-0.635) 13(4.75,0.635) 14(4.75,1.905) 15(4.75,3.175) 16(4.75,4.445)
SOT223
  rect 1.499x2.007 smd: 1(-2.3,-3.15) 2(0,-3.15) 3(2.3,-3.15)
  rect 3.81x2.007 smd: 4(0,3.15)
SOT-23-BCE
  rect 0.813x1.016 smd: B(-0.95,-1.1) C(0,1.1) E(0.95,-1.1)
T2PAK_7L
  rect 0.9x3 smd: 1(-3.819,0.029) 2(-2.549,0.029) 3(-1.279,0.029) 4(0.001,0.009) 5(1.261,0.029) 6(2.531,0.029) 7(3.801,0.029)
  rect 2.5x1.5 smd: 8(-6.046,16.663) 9(6.154,16.663)
T4_700X850X600
  rect 1.626x1.067 smd: 1(-3.645,1.85) 2(-3.645,0) 3(-3.645,-1.85) 4(3.645,-1.85) 5(3.645,0) 6(3.645,1.85)
TEST_270X100_SMT
  rect 3.048x1.524 smd: 1(0,0)
TO252AB
  rect 1.6x2.997 smd: 1(2.3,-7.16) 3(-2.3,-7.16)
  rect 6.706x6.706 smd: 2(0,-0.51)
unnamed#2
  round 1.016 smd: 1(0,0)
unnamed#3
  round 5.74 hole 5.994 unplated: (0,0)

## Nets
+15V: C53.2 C60.1 C64.1 C91.2 C104.1 C107.1 C119.2 C120.2 C128.1 L1.1 R97.2 R128.2 U8.8 U12.8
+15V_L: C57.1 C62.1 Q7.E R68.2 R89.2 R96.1 R102.2
+15V_U_H: C37.1 C43.1 C44.1 C76.1 C81.1 Q8.E R93.1 R113.1 U4.5
+15V_V_H: C79.1 C85.1 C86.1 C92.1 C98.1 Q9.E R57.1 R125.1 U10.5
+15V_W_H: C94.1 C100.1 C101.1 C111.1 C115.1 Q10.E R135.1 R137.1 U11.5
-3V_L: C27.2 C28.2 C29.2 C50.2 C51.2 C52.2 C59.2 C61.2 C62.2 C63.2 C67.2 C71.2 C72.2 C73.2 D7.1 D8.1 D9.1 U2.8 U7.8 U9.8
-3V_U_H: C43.2 C44.2 C45.2 C78.2 C80.2 C81.2 C83.2 C87.2 D11.1 D12.1 D13.1 U4.8
-3V_V_H: C85.2 C86.2 C88.2 C95.2 C97.2 C98.2 C102.2 C105.2 D17.1 D18.1 D19.1 U10.8
-3V_W_H: C100.2 C101.2 C106.2 C113.2 C114.2 C115.2 C116.2 C118.2 D23.1 D24.1 D25.1 U11.8
AGND: C17.1 C18.1 C19.2 C20.2 C21.2 C22.2 C25.2 C30.2 C31.1 C32.2 C33.2 C34.1 C36.1 C38.2 C40.2 C41.2 C48.2 C53.1 C55.1 C56.1 C64.2 C65.2 C66.2 C68.2 C69.2 C74.2 C75.1 C82.2 C84.2 C89.2 C90.1 C91.1 C96.2 C99.2 C107.2 C108.2 C109.2 C119.1 C120.1 C121.1 C122.1 C123.1 C124.2 C125.2 C126.2 C127.2 C128.2 C129.2 D28.1 J1.17 L1.2 R35.2 R36.1 R37.1 R38.1 R39.1 R40.1 R51.1 R61.1 R63.1 R69.2 R75.2 R77.1 R84.1 R88.1 R90.2 R103.2 R104.2 R105.2 R106.2 R107.1 R112.2 R121.2 R131.2 R132.2 R133.2 R143.1 RJ1.1 U1.9 U1.10 U1.11 U2.3 U2.4 U3.9 U3.10 U3.11 U4.9 U4.11 U5.9 U5.10 U5.11 U6.2 U7.3 U7.4 U8.6 U8.9 U9.3 U9.4 U10.9 U10.11 U11.9 U11.11 U12.6 U12.9 U13.1
AGND_U: J1.2 R88.2
AGND_V: J1.8 R51.2
AGND_W: J1.12 R84.2
DGND: J2.1 J2.3
P6.5V: C42.1 C46.1 C47.1 CN2.10 U6.3
VIN+: J1.16 R43.1
VIN-: J1.14 R44.1
A_3.3V: J1.19 NTC1.1 R79.1
CAN+5V: CN3.1 J2.11
CAN_GND: CN3.2 J2.12
CLAMP_U_L: C6.1 PAD18.1 Q6.7 R26.2 R29.2 R34.1 U2.7
CLAMP_V_L: C4.1 PAD17.1 Q5.7 R25.2 R28.2 R31.1 U7.7
CLAMP_W_L: C5.1 PAD16.1 Q4.7 R24.2 R24_2.2 R27.2 R27_2.2 R30.1 U9.7
DESAT_U: C54.1 R94.1 R95.2 U4.2
DESAT_V: C103.1 R124.1 R130.2 U10.2
DESAT_W: C117.1 R136.1 R139.2 U11.2
DRV_U_H: C1.1 PAD4.1 Q1.7 R8.1 R71.2 R74.2 U4.7
DRV_U_L: D3.1 R29.1 U2.6
DRV_V_H: C3.1 PAD6.1 Q2.7 R7.1 R109.2 R111.2 U10.7
DRV_V_L: D2.1 R28.1 U7.6
DRV_W_H: C2.1 PAD5.1 Q3.7 R6.1 R118.2 R118_2.2 R120.2 R120_2.2 U11.7
DRV_W_L: D1.1 D1_2.1 R27.1 R27_2.1 U9.6
FAULT: C31.2 C75.2 C90.2 J1.18 R80.1 R114.1 R123.1
G_L: C26.2 C29.1 C49.2 C52.1 C57.2 C67.1 C70.2 C73.1 D9.2 R54.1 R55.1 R56.1 R96.2
G_U_H: C1.2 C37.2 C45.1 C54.2 C76.2 C87.1 D13.2 PAD12.1 Q1.6 R8.2 R95.1 R113.2 U4.3
G_V_H: C3.2 C79.2 C88.1 C92.2 C103.2 C105.1 D19.2 PAD7.1 Q2.6 R7.2 R125.2 R130.1 U10.3
G_W_H: C2.2 C94.2 C106.1 C111.2 C117.2 C118.1 D25.2 PAD9.1 Q3.6 R6.2 R137.2 R139.1 U11.3
IGND: C35.2 CN1.2 CN2.2
IPH_U+: C15.1 J1.21 R42.2
IPH_U-: C7.2 C8.2 C9.2 C10.2 C11.2 C12.2 C13.2 C14.2 C15.2 C16.2 C130.2 C131.2 C133.2 C134.2 C135.2 C136.2 C137.2 C138.2 C139.2 C140.2 CON2.1 CON2.2 CON2.3 CON2.4 J1.23 J1.24 J1.26 R2.2 R35.1 R48.2 R49.2 R50.2 R52.2 R53.2 R2512.2
IPH_V+: C14.1 J1.25 R41.2
IPH_W+: C16.1 J1.22 R85.1
IU+: C24.1 J1.3 U3.12
IU-: C24.2 J1.1 R36.2
IU_OCP: R65.2 U3.13
IV+: C23.1 J1.7 U1.12
IV-: C23.2 J1.5 R37.2
IV_OCP: R64.2 U1.13
IW+: C39.1 J1.11 U5.12
IW-: C39.2 J1.9 R143.2
IW_OCP: R78.2 U5.13
NETC4_2: C4.2 PAD19.1 Q5.6 R31.2 R55.2
NETC5_2: C5.2 PAD20.1 Q4.6 R30.2 R54.2
NETC6_2: C6.2 PAD22.1 Q6.6 R34.2 R56.2
NETC7_1: C7.1 C8.1 C9.1 C10.1 C11.1 C12.1 C13.1 C130.1 C131.1 C133.1 C134.1 C135.1 C136.1 C137.1 C138.1 C139.1 C140.1 CON1.1 CON1.2 CON1.3 CON1.4 D5.2 D15.2 D21.2 PAD1.1 PAD2.1 PAD3.1 Q1.8 Q1.9 Q2.8 Q2.9 Q3.8 Q3.9 R1.2
NETC17_2: C17.2 C18.2 R66.2 U2.1
NETC19_1: C19.1 C21.1 R58.1 R60.1 R64.1 U1.15 U1.16
NETC20_1: C20.1 C22.1 R59.1 R62.1 R65.1 U3.15 U3.16
NETC25_1: C25.1 R67.2 R69.1 U2.2
NETC26_1: C26.1 C27.1 C28.1 R68.1 U2.5
NETC30_1: C30.1 R72.2 R75.1 U4.10 U4.14
NETC32_1: C32.1 C33.1 R73.1 R76.1 R78.1 U5.15 U5.16
NETC34_2: C34.2 C36.2 R83.2 U7.1
NETC35_1: C35.1 CN1.1 CN2.1
NETC38_1: C38.1 C40.1 R70.1 R81.2 U4.15
NETC48_1: C48.1 R86.2 R90.1 U7.2
NETC49_1: C49.1 C50.1 C51.1 R89.1 U7.5
NETC55_2: C55.2 C56.2 R99.2 U9.1
NETC58_1: C58.1 C59.1 C61.1 D6.2 Q7.C R98.2
NETC58_2: C58.2 C63.1 T1.4
NETC60_2: C60.2 C69.1 R97.1 R107.2 T1.3
NETC65_1: C65.1 R100.2 U8.3
NETC66_1: C66.1 R105.1 U8.5
NETC68_1: C68.1 R101.2 R103.1 U9.2
NETC70_1: C70.1 C71.1 C72.1 R102.1 U9.5
NETC74_1: C74.1 R110.2 R112.1 U10.10 U10.14
NETC77_1: C77.1 C78.1 C80.1 D10.2 Q8.C R115.2
NETC77_2: C77.2 C83.1 T2.4
NETC82_1: C82.1 C84.1 R108.1 R116.2 U10.15
NETC89_1: C89.1 R119.2 R121.1 U11.10 U11.14
NETC93_1: C93.1 C95.1 C97.1 D16.2 Q9.C R126.2
NETC93_2: C93.2 C102.1 T3.4
NETC96_1: C96.1 C99.1 R117.1 R127.2 U11.15
NETC104_2: C104.2 C110.1 R128.1 R134.2 T2.3 T3.3 T4.3
NETC108_1: C108.1 R131.1 U12.5
NETC109_1: C109.1 R129.2 U12.3
NETC110_2: C110.2 R134.1 RJ1.2
NETC112_1: C112.1 C113.1 C114.1 D22.2 Q10.C R138.2
NETC112_2: C112.2 C116.1 T4.4
NETC121_2: C121.2 R70.2 U4.12
NETC122_2: C122.2 R108.2 U10.12
NETC123_2: C123.2 R117.2 U11.12
NETCN2_5: CN2.5 L1.4
NETCN2_6: CN2.6 L1.3
NETCON3_1: CON3.1 CON3.2 CON3.3 CON3.4 R4.2 U1.5 U1.6 U1.7 U1.8
NETCON4_1: CON4.1 CON4.2 CON4.3 CON4.4 R5.2 U5.5 U5.6 U5.7 U5.8
NETCON5_1: CON5.1 CON5.2 CON5.3 CON5.4 R3.2 U3.5 U3.6 U3.7 U3.8
NETD1_2: D1.2 R24.1
NETD1_2_2: D1_2.2 R24_2.1
NETD2_2: D2.2 R25.1
NETD3_2: D3.2 R26.1
NETD4_1: D4.1 R140.2
NETD4_2: D4.2 D5.1
NETD6_1: D6.1 D8.2 T1.6
NETD7_2: D7.2 Q7.B R98.1
NETD10_1: D10.1 D12.2 T2.6
NETD11_2: D11.2 Q8.B R115.1
NETD14_1: D14.1 R141.2
NETD14_2: D14.2 D15.1
NETD16_1: D16.1 D18.2 T3.6
NETD17_2: D17.2 Q9.B R126.1
NETD20_1: D20.1 R142.2
NETD20_2: D20.2 D21.1
NETD22_1: D22.1 D24.2 T4.6
NETD23_2: D23.2 Q10.B R138.1
NETD26_1: D26.1 D27.2
NETD27_1: D27.1 D28.2
NETPAD8_1: PAD8.1 PAD13.1 Q2.1 Q2.2 Q2.3 Q2.4 Q2.5 Q5.8 Q5.9 U1.1 U1.2 U1.3 U1.4
NETPAD10_1: PAD10.1 PAD14.1 Q3.1 Q3.2 Q3.3 Q3.4 Q3.5 Q4.8 Q4.9 U5.1 U5.2 U5.3 U5.4
NETPAD11_1: PAD11.1 PAD15.1 Q1.1 Q1.2 Q1.3 Q1.4 Q1.5 Q6.8 Q6.9 U3.1 U3.2 U3.3 U3.4
NETPAD21_1: PAD21.1 Q4.1 Q4.2 Q4.3 Q4.4 Q4.5 R52.1 R53.1 R85.2
NETPAD23_1: PAD23.1 Q6.1 Q6.2 Q6.3 Q6.4 Q6.5 R42.1 R50.1 R2512.1
NETPAD24_1: PAD24.1 Q5.1 Q5.2 Q5.3 Q5.4 Q5.5 R41.1 R48.1 R49.1
NETR1_1: R1.1 R9.2
NETR2_1: R2.1 R10.2
NETR3_1: R3.1 R11.2
NETR4_1: R4.1 R12.2
NETR5_1: R5.1 R13.2
NETR9_1: R9.1 R14.2
NETR10_1: R10.1 R15.2
NETR11_1: R11.1 R16.2
NETR12_1: R12.1 R17.2
NETR13_1: R13.1 R18.2
NETR14_1: R14.1 R19.2
NETR15_1: R15.1 R20.2
NETR16_1: R16.1 R21.2
NETR17_1: R17.1 R23.2
NETR18_1: R18.1 R22.2
NETR19_1: R19.1 R32.2
NETR20_1: R20.1 R33.2
NETR21_1: R21.1 R45.2
NETR22_1: R22.1 R47.2
NETR23_1: R23.1 R46.2
NETR32_1: R32.1 R43.2
NETR33_1: R33.1 R44.2
NETR57_2: R57.2 R122.1
NETR60_2: R60.2 R61.2 U1.14
NETR62_2: R62.2 R63.2 U3.14
NETR71_1: R71.1 U4.6
NETR74_1: R74.1 U4.4
NETR76_2: R76.2 R77.2 U5.14
NETR80_2: R80.2 U4.13
NETR93_2: R93.2 R94.2 R140.1
NETR100_1: R100.1 R106.1 U8.4
NETR104_1: R104.1 U8.1
NETR109_1: R109.1 U10.6
NETR111_1: R111.1 U10.4
NETR114_2: R114.2 U10.13
NETR118_1: R118.1 R118_2.1 U11.6
NETR120_1: R120.1 R120_2.1 U11.4
NETR122_2: R122.2 R124.2 R141.1
NETR123_2: R123.2 U11.13
NETR129_1: R129.1 R133.1 U12.4
NETR132_1: R132.1 U12.1
NETR135_2: R135.2 R136.2 R142.1
NETRJ0_1: RJ0.1 T4.1
NETRJ0_2: RJ0.2 T2.1 T3.1 U12.7
NETT1_1: T1.1 U8.7
P_-2.7V: C42.2 C46.2 C47.2 C129.1 CN2.9 D26.2 J1.20
PWM-U-H: J2.2 R72.1
PWM-U-L: J2.4 R67.1
PWM-V-H: J2.6 R110.1
PWM-V-L: J2.8 R86.1
PWM-W-H: J2.5 R119.1
PWM-W-L: J2.7 R101.1
TEMP: J1.13 NTC1.2
U_SAMPLE: J1.4 R38.2 R45.1
V_SAMPLE: J1.6 R39.2 R46.1
VA+3.3V: C125.1 C126.1 R58.2 R59.2 R73.2 R79.2 U13.2
VA+5V: C41.1 C124.1 C127.1 J1.15 R66.1 R81.1 R83.1 R99.1 R116.1 R127.1 U6.1 U13.3
VS+15V: CN3.4
VS_GND: CN3.5
W_SAMPLE: J1.10 R40.2 R47.1

Pads without a net: CN2 3 4 7 8; CN3 3; J2 9 10; NOREF#3 1; NOREF#4 1; NOREF#5 1; NOREF#9 1; NOREF#12 1; NOREF#13 1; T1 2 5; T2 2 5; T3 2 5; T4 2 5; U4 1 16; U8 2; U10 1 16; U11 1 16; U12 2; U13 4

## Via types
v1: diameter 0.508, hole 0.254, TOP to BOTTOM, 1559 vias
v2: diameter 0.559, hole 0.305, TOP to BOTTOM, 1 via

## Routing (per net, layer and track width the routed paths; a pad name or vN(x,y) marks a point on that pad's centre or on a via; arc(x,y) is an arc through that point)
+15V: length 198.6
  GND03 w1.27: L1.1 47.91,82.01 54.35,80.11 56,80.11 v1(58.26,79.5)
  PWM04 w0.889: 110.45,124.58 90.13,124.58
  PWM04 w1.016: 110.45,124.58 118.58,116.45 118.58,113.91 121.25,111.25 121.25,107.44 v1(122.39,106.29) ; 90.13,124.58 89.12,125.6 89.12,127.63 86.96,129.79 76.29,129.79 71.59,125.09 51.51,125.09 49.23,122.8 40.94,122.8 32.24,111.07 32.24,107.09 39.16,100.17 39.16,95.19 38.04,94.08 34.58,94.08 33.03,92.53 L1.1
  BOTTOM w0.381: 75.5,66.48 75.88,66.86 U12.8
  BOTTOM w0.508: 73.17,68.26 C91.2 ; 75.5,66.48 C104.1
  BOTTOM w0.762: C107.1 69.24,68.26 73.17,68.26 ; C104.1 R128.2 73.3,66.51 C91.2 C120.2 ; C128.1 L1.1
  BOTTOM w1.27: C107.1 68.67,68.39 67.4,69.66 67.4,70.36 v1(58.26,79.5)
+15V_L: length 366.8
  TOP w0.508: R89.2 61.96,26.92 v1(60.29,26.92)
  TOP w0.762: R96.1 C57.1 v1(124.62,84.62)
  TOP w1.016: R102.2 C57.1 ; v1(45.68,98.04) 45.8,97.92 R68.2
  TOP w1.27: v1(29.56,96.26) 29.56,97.53 20.16,106.93 20.16,112.26 v1(23.21,115.31)
  VCC02 w1.016: v1(45.68,98.04) 31.33,98.04 v1(29.56,96.26) 29.56,96.02 21.81,88.28 12.19,82.21 8.49,78.23 6.69,78.23 4.49,76.03 4.49,67.78 4.65,63.97 4.66,63.63 4.66,59.47 4.66,59.46 4.7,58.56 8.13,47.56 8.74,46.39 8.82,46.15 16.04,31.81 35.99,18.83 43.4,20.06 50.64,20.06 56.54,23.17 v1(60.29,26.92) ; v1(23.21,115.31) 23.21,115.69 38.05,130.54 42.53,133.61 44.06,134.25 45.78,134.17 51.66,132.33 82.08,132.33 90.14,124.26 111.78,124.26 117.56,118.64 117.56,108.84 126.58,99.82 126.58,86.59 v1(124.62,84.62)
  I_SAMPLING05 w0.762: 40.86,133.09 39.59,133.19
  I_SAMPLING05 w1.27: v1(23.21,115.31) 30.98,127.61 32.69,128.97 39.59,133.19
  BOTTOM w0.762: v1(124.62,84.62) Q7.E 127.07,82.51 127.82,82.64 130.13,83.23 C62.1
+15V_U_H: length 28.3
  TOP w0.711: C76.1 109.16,107.97 ; C76.1 110.73,107.94 ; C76.1 108.5,108.58 v1(107.08,108.58) ; 110.7,112.87 110.46,112.64 C81.1
  TOP w0.762: R93.1 110.73,106.11 110.73,112.85 110.7,112.87 110.7,115.46 109.94,116.22 Q8.E ; C44.1 102.65,110.47 C43.1 102.66,109.09 C37.1 103.08,108.67 R113.1 105.22,108.58 v1(107.08,108.58)
  BOTTOM w0.635: U4.5 106.61,109.96 107.08,109.5 v1(107.08,108.58)
+15V_V_H: length 30.5
  TOP w0.152: 24.21,72.64 C86.1
  TOP w0.762: R125.1 C92.1 25.57,77.41 27.19,77.01 28.49,74.09 28.69,73.6 28.36,73.07 C79.1 C85.1 24.21,72.64 ; R125.1 23.59,79.35 21.78,79.75 18.86,78.52 ; R125.1 R57.1 ; v1(24.35,74.11) 24.05,73.21 C86.1 ; Q9.E 15.87,77.27 18.86,78.52 ; 18.86,78.52 C98.1
  BOTTOM w0.762: v1(24.35,74.11) U10.5
+15V_W_H: length 26.7
  TOP w0.635: C94.1 C101.1 v1(109.82,25.7)
  TOP w0.762: 106.71,23.42 105.77,21.88 R137.1 105.54,20.93 106.15,19.91 106.67,19.63 107.39,19.34 C115.1 ; 106.71,23.42 v1(107.58,23.02) ; 106.71,23.42 107.09,24.78 C111.1 Q10.E 105.64,26.27 104.82,27.09 104.82,29 R135.1 ; C100.1 C101.1
  PWM04 w1.27: v1(107.58,23.02) 109.92,25.78
  BOTTOM w0.762: v1(109.82,25.7) U11.5 108.37,23.03 108.28,23.02 v1(107.58,23.02)
-3V_L: length 364.8
  TOP w0.508: v1(50.24,91.07) 49.81,91.5 C29.2 48.99,92.92 C27.2 47.61,92.93 C28.2 ; C72.2 113.21,83.77 C71.2 C73.2 110.99,82.37 v1(110.41,82.16)
  TOP w0.762: 64.62,30.13 C50.2 ; C50.2 63.74,32.2 v1(62.75,32.41) ; C50.2 C52.2 v1(65.29,33.47) ; v1(131.79,89.02) 130.76,88.95 129.81,87.87 C67.2 ; C67.2 129.86,87.04 129.7,86.58 129.2,85.85 124.39,83.36 120.49,82.16 117.82,80.51 116.89,79.48 115,78.5 112.29,79.79 111.85,80.97 C71.2 ; C67.2 130.31,88.47 D9.1
  VCC02 w0.762: 62.75,32.43 v1(62.75,32.41)
  VCC02 w1.016: v1(131.79,89.02) 131.46,87.47 125.24,83.45 125.15,83.35 123.37,83.35 122.52,84.19 122.4,88.81 122.4,90.8 123.66,92.06 123.66,96.26 114.86,105.07 114.86,117.48 110.79,121.56 88.2,121.56 86.2,123.57 53.09,123.57 50.85,121.36 50.85,112.16 48.22,108.07 48.22,93.09 v1(50.24,91.07) 49.47,90.29 45.04,90.29 43.39,91.94 40.6,91.94 38.92,93.63 32.37,93.63 28.16,89.42 28.16,88.64 26.19,86.67 23.09,84.98 16.35,80.51 11.01,75.43 10.52,74.22 9.81,69.04 9.81,68.14 7.97,66.29 7.97,58.42 9.62,53.12 11.52,47.11 18.32,33.89 36.79,22.23 43.02,23.36 49.59,23.49 55.91,26.61 58.52,29.22 61.18,30.49 62.46,31.3 v1(62.75,32.41)
  BOTTOM w0.508: U2.8 v1(50.24,91.07)
  BOTTOM w0.762: D7.1 C59.2 126.58,90.46 126.37,90.6 C61.2 ; D7.1 D8.1 130.47,93.73 128.78,94.83 C63.2 ; D7.1 131.78,91.17 132.77,90.52 133.54,87.41 C62.2 132.26,88.66 v1(131.79,89.02) ; U2.8 50.26,91.08 ; v1(65.29,33.47) U7.8 ; U9.8 v1(110.41,82.16)
-3V_U_H: length 22.7
  TOP w0.711: 106.26,115.34 D13.1 106.27,114.3 105.98,114.3 ; 106.26,115.34 v1(104.94,115.34) ; 106.26,115.34 106.03,115.56 D11.1
  TOP w0.762: C83.2 103.42,115.34 v1(104.94,115.34) ; 105.98,114.3 C87.2 v1(103.7,114.3) 102.79,113.39 C45.2 102.66,112.01 C43.2 102.65,111.99 C44.2 ; D13.1 108.88,114.81 C81.2
  BOTTOM w0.762: 104.94,116.14 104.72,115.92 C78.2 ; 104.94,116.14 v1(104.94,115.34) ; 104.94,116.14 C80.2 ; U4.8 104.24,113.77 v1(103.7,114.3) ; 103.42,115.89 C78.2 ; C78.2 101.89,115.92 D12.1
-3V_V_H: length 31.8
  TOP w0.762: C86.2 C85.2 C88.2 20.84,69.69 20.06,69.95 19.62,70.89 v1(19.76,71.57) C105.2 D19.1 ; v1(15.56,71.06) 16.42,69.74 D17.1 18.43,70.46 18.21,72.54 D19.1 ; D19.1 C98.2
  BOTTOM w0.762: C102.2 18.36,70.47 17.49,70.99 v1(15.56,71.06) D18.1 14.23,71.46 14.85,72.49 C95.2 C97.2 ; v1(19.76,71.57) 20.74,72.74 U10.8
-3V_W_H: length 37.7
  TOP w0.762: C106.2 C118.2 D25.1 C115.2 v1(111.97,19.18) ; C106.2 C101.2 C100.2 ; C106.2 113.6,25.05 113.94,24.03 v1(113.73,23.62) ; C113.2 C116.2 v1(101.03,24.94) D23.1 ; C113.2 C114.2 ; C113.2 D24.1
  I_SAMPLING05 w1.27: v1(101.03,24.94) v1(111.97,19.18)
  BOTTOM w0.762: v1(113.73,23.62) 113.2,22.98 U11.8
AGND: length 145.6
  TOP w0.381: U8.6 120.39,106.11 U8.9
  TOP w0.508: v1(52.58,137.59) R39.1 R51.1 ; R84.1 R40.1 v1(60.21,136.93) ; R88.1 43.79,134.83 R38.1 46.04,135.49 v1(46.04,135.5)
  TOP w0.762: C55.1 C56.1 v1(118.33,87.5) ; v1(65.6,23.31) C34.1 C36.1 v1(65.17,24.18)
  TOP w1.27: v1(42.26,89.53) 32.35,89.53 v1(24.33,97.55)
  VCC02 w1.27: v1(42.26,89.53) 42.26,88.77 48.99,82.04 50.89,82.04 52.3,80.63 v1(59.45,80.63)
  PWM04 w0.508: v1(22.19,90.55) v1(23.46,91.18)
  I_SAMPLING05 w1.27: v1(24.33,97.55) L1.2
  BOTTOM w0.381: 77.33,68.79 77.18,68.65 U12.6 ; 118.42,112.37 116.63,112.37 115.49,111.23 U4.11 ; 118.58,105.91 117.69,105.91 117.31,106.42 C31.1 ; U11.11 105.74,14.17 105.09,14.16 103.95,14.16 103.87,14.2 103.52,14.07 103.01,12.97 102.71,12.54 ; 16.1,86.14 16.69,84.86 17.05,84.51 17.94,84.51 18.58,83.61 U10.11
  BOTTOM w0.508: R37.1 v1(25.2,41.87) ; C32.2 C33.2 v1(130.01,38.98) ; R77.1 v1(130.99,42.27) ; U11.11 106.77,16.25 107.25,16.59 107.67,16.64 108.67,16.17 108.86,15.27 U11.9 ; U4.9 113.55,113.77 113.07,113.29 113.07,111.88 113.73,111.23 U4.11 ; 21.91,88.86 22.24,88.15 22.07,87.67 C75.1 ; v1(21.28,42.71) R61.1 ; U10.11 19.14,82.28 19.15,82.23 18.96,81.78 17.49,80.95 16.86,81.2 U10.9 ; R143.1 U5.11 ; C38.2 119.35,103.5
  BOTTOM w0.762: 62.43,2.37 v1(62.42,2.36) ; 62.43,2.37 v1(61.46,2.37) ; 62.43,2.37 R35.2 ; C90.1 97.42,16.25 ; R103.2 C68.2 ; v1(77.44,126.89) R63.1 ; C19.2 C21.2 v1(19.49,46.91) ; R69.2 42.13,93.73 C25.2 43.52,93.7 U2.3 43.71,94.76 U2.4 ; C128.2 L1.2 ; C20.2 C22.2 v1(82.01,127) ; R90.2 C48.2 U7.3 U7.4 v1(65.17,24.18)
  BOTTOM w1.27: v1(59.45,80.63) 66.8,73.27 69.18,73.27
  vias: v1(27.4,40.38) v1(27.78,39.11) v1(28.54,40.89) v1(28.79,39.62) v1(41.87,94.63) v1(42.51,95.12) v1(71.57,122.42) v1(71.57,121.15) v1(71.57,73.62) v1(71.57,71.08) v1(72.74,122.42) v1(72.74,121.15) v1(97.25,18.54) v1(97.75,18.03) v1(98.39,17.78) v1(117.56,87.81) v1(119.09,105.91) v1(119.47,114.68) v1(119.8,114.04) v1(119.85,103.5) v1(122.67,109.92) v1(123.01,109.3) v1(128.23,49.02) v1(128.74,50.16) v1(129.5,48.38) v1(130.01,49.53)
AGND_U: length 4
  TOP w0.381: J1.2 41.41,130.49 R88.2
AGND_V: length 7.2
  TOP w0.381: J1.8 47.77,130.81 49.88,132.92 49.88,134.47 50.26,134.85 R51.2
AGND_W: length 8
  TOP w0.381: J1.12 52.85,130.58 57.39,135.12 R84.2
DGND: length 2.5
  BOTTOM w0.508: J2.1 J2.3
VIN+: length 14.4
  TOP w0.508: R43.1 v1(47.64,124.33)
  GND03 w0.508: v1(47.64,124.33) 48.53,125.22 50.76,125.22 51.58,126.03 51.58,127.45 52.08,127.96 56.68,127.96 57.93,129.2 J1.16
VIN-: length 15.4
  TOP w0.508: v1(44.03,124.21) 43.96,124.14 R44.1
  BOTTOM w0.381: J1.14 54.12,127.96 52.11,127.96 51.58,127.43 51.58,126.16 50.83,125.42 47.28,125.42 46.07,124.2 44.03,124.2 v1(44.03,124.21)
A_3.3V: length 27.8
  TOP w0.254: 64.28,129.92 64.28,127.96 J1.19
  TOP w0.381: 64.28,129.92 64.28,130.43 64.66,130.81 77.2,130.81 NTC1.1
  BOTTOM w1.27: R79.1 61.83,124.38 63.01,125.56 J1.19
CAN+5V: length 93
  I_SAMPLING05 w0.508: v1(96.94,133.73) 91.79,133.73 90.07,133.74 77.69,133.74 76.55,134.87 54.14,134.87 52.75,133.47 44.77,133.47 38.2,130.88 33.94,125.86 30.87,119.43 CN3.1
  BOTTOM w0.508: v1(96.94,133.73) 98.54,133.73 100.68,131.59 103.71,131.59 105.55,129.75 105.55,129.74 105.71,129.58 105.71,128.73 104.28,127.3 J2.11
CAN_GND: length 84.4
  I_SAMPLING05 w0.508: CN3.2 31.95,119.37 34.73,125.61 38.05,129.52 38.72,130.19 44.98,132.71 53.06,132.71 54.46,134.11 75.66,134.11 76.79,132.97 90.07,132.97 92.81,132.97 v1(97.86,132.94)
  BOTTOM w0.508: v1(97.86,132.94) 99.98,130.82 102.69,130.82 J2.12
CLAMP_U_L: length 1.9
  TOP w0.762: v1(52.85,91.85) PAD18.1
  vias: v1(51.91,94.23) v1(51.91,93.34) v1(52.8,94.23) v1(52.8,93.34)
CLAMP_V_L: length 2
  TOP w0.508: PAD17.1 62.15,35.02 v1(63.08,35.81)
  vias: v1(60.94,34.59) v1(61.32,33.83) v1(61.85,35.04) v1(62.23,34.28)
CLAMP_W_L: length 5.3
  TOP w0.508: v1(109.57,78.48) 110.23,78.1 PAD16.1 ; R24_2.2 v1(105.83,80.82) R27_2.2
  vias: v1(111.13,77.92) v1(111.51,78.72) v1(112.16,77.34) v1(112.54,78.14)
DESAT_U: length 6.6
  TOP w0.762: v1(102.81,105.41) 103.09,105.69 R95.2 104.01,105.67 C54.1 105.24,105.68 R94.1
  BOTTOM w0.711: U4.2 103.55,106.15 v1(102.81,105.41)
DESAT_V: length 7.7
  BOTTOM w0.762: U10.2 28.01,75.48 29.33,75.26 R130.2 C103.1 R124.1
DESAT_W: length 6.4
  TOP w0.762: R136.1 106.77,31.04 C117.1 R139.2 106.09,28.17 v1(106.14,27.94)
  BOTTOM w0.762: U11.2 106.25,27 v1(106.14,27.94)
DRV_U_H: length 2.5
  TOP w0.762: PAD4.1 100.04,106.31 v1(99.02,107.32)
  vias: v1(99.63,105.4) v1(99.63,104.64) v1(100.52,105.4) v1(100.52,104.64)
DRV_U_L: length 7.9
  BOTTOM w0.508: 47.46,92.65 47.46,92.71
  BOTTOM w0.762: U2.6 47.97,93.59 47.46,92.71 ; D3.1 47.46,92.65
  BOTTOM w1.27: D3.1 R29.1
DRV_V_H: length 6.7
  TOP w0.762: v1(28.37,69.79) PAD6.1
  BOTTOM w0.762: R111.2 Q2.7
  vias: v1(31.14,72.61) v1(31.51,71.81) v1(31.83,72.94) v1(32.21,72.13)
DRV_V_L: length 9.1
  BOTTOM w0.762: U7.6 63.68,30.44 64.31,30.11 67.28,31.45 ; R28.1 D2.1 ; D2.1 67.28,31.45 ; D2.1 67.28,31.45
DRV_W_H: length 22.9
  TOP w0.762: v1(114.89,29.04) R118_2.2 R120_2.2
  PWM04 w0.762: v1(114.89,29.04) 103.23,32.39 v1(101.57,32.39)
  BOTTOM w0.508: R118.2 v1(114.89,29.04)
  BOTTOM w0.762: R118.2 113.5,29.79 113.3,30.73 R6.1
  vias: v1(100.84,32.77) v1(101.22,33.53) v1(101.95,33.16)
DRV_W_L: length 15.3
  TOP w0.508: v1(110.51,85.01) D1_2.1 R27_2.1
  BOTTOM w0.508: 113.35,83.66 110.87,84.82 v1(110.51,85.01) ; 113.6,82.99 U9.6
  BOTTOM w0.762: R27.1 D1.1 v1(110.51,85.01) 113.35,83.66 113.6,82.99 U9.6
FAULT: length 277.3
  VCC02 w0.508: v1(20.28,89.78) 37.24,106.74 39.4,106.74 42.89,110.23 45.13,110.23 48.56,113.66 48.56,122.64 51.58,125.61 51.58,127.21 52.32,127.96 59.2,127.96 J1.18 ; v1(124.55,29.46) 122.89,27.76 122.91,25.75 122.41,25.25 112.11,15.05 100.49,15.05 v1(98.52,13.08)
  I_SAMPLING05 w0.381: v1(109.59,125.98) 108.7,125.09 88.99,125.09 85.59,128.49 75.68,128.49 72.86,131.31 62.55,131.31 J1.18
  BOTTOM w0.508: R114.1 C75.2 20.28,89.35 v1(20.28,89.78)
  BOTTOM w0.762: 124.62,113.4 121.82,110.8 119.32,108.3 R80.1 C31.2 ; 124.62,113.4 128.1,110.01 134.08,98.29 139.9,82.13 140.66,70.65 140.66,66.39 138.7,54 137.63,49.4 136.36,45.84 135.09,42.79 133.06,38.48 131.75,36.14 128.63,31.53 126.98,29.52 124.74,29.3 v1(124.55,29.46) ; 124.62,113.4 111.69,126 109.59,125.98 v1(109.59,125.98) ; v1(98.52,13.08) R123.1 C90.2
G_L: length 312.6
  TOP w0.508: C26.2 46.18,91.96 v1(46.57,91.56) 46.66,91.48 C29.1
  TOP w0.762: 66.41,29.89 66.31,29.79 66.31,29.51 v1(66,29.21) 65.94,29.23 C49.2 ; 66.41,29.89 66.39,29.9 66.32,29.97 66.04,30.59 C52.1 ; 66.41,29.89 66.41,29.83 66.44,29.83 v1(66.44,29.83) ; v1(123.71,89.56) 124.9,89.25 R96.2 C57.2 C67.1 D9.2 ; v1(103.49,83.92) v1(102.94,84.15)
  VCC02 w1.016: v1(66.44,29.83) 66.44,29.64 v1(66,29.21) 65.12,28.32 59.89,28.32 56.72,25.15 50.13,21.71 43.27,21.71 36.04,20.63 17,33.03 10.09,46.51 10.1,46.54 9.92,46.87 9.79,47.13 6.73,56.91 6.37,57.63 6.37,66.86 8.48,68.96 9.53,76.64 13.24,80.52 22.81,87.08 25.28,89.58 26.46,89.86 31.54,94.94 39.77,94.94 41.37,93.35 44.1,93.35 45.62,91.56 v1(46.57,91.56) 46.95,91.94 46.95,109.09 49.58,112.69 49.58,121.89 52.83,125.09 87.09,125.09 89.29,122.89 111.36,122.89 116.29,117.95 116.29,105.54 124.93,96.9 124.93,90.79 v1(123.71,89.56)
  I_SAMPLING05 w1.016: v1(112.89,85.29) 117.19,84.96 120.49,86.48 v1(123.71,89.56)
  BOTTOM w1.27: R54.1 103.27,84.07 ; R55.1 71.57,37.51
  vias: v1(46.19,92.05) v1(51.65,84.2) v1(51.68,83.51) v1(71.28,37.37) v1(71.88,37.65) v1(112.08,85.31)
G_U_H: length 40.3
  TOP w0.711: 101.19,108.35 C37.2 ; 108.27,110.2 R113.2 105.12,111.68
  TOP w0.762: v1(102.83,104.14) 103.22,104.14 R95.1 104.01,104.15 C54.2 ; C76.2 108.91,110.2 108.27,110.2 108.26,110.21 v1(108.26,111.35) 106.94,111.35 D13.2 106.74,111.47 105.33,111.47 104.8,112 C87.1 ; v1(96.38,107.33) PAD12.1 ; v1(101.14,114.17) C45.1 100.54,113.39 100.04,112.89 100.04,109.58 100.57,109.04 C37.2 ; v1(101.51,107.29) 101.19,108.35
  BOTTOM w0.762: U4.3 104.98,107.14 103.14,107.14 103.06,107.06 101.74,107.06 v1(101.51,107.29) 101.51,107.24 101.54,107.21 100.81,106.48 97.16,106.48 96.4,107.24 v1(96.38,107.33) Q1.6 96.4,111.66 96.4,111.66 C1.2 96.4,113.01 96.41,113.02 R8.2
  vias: v1(96.2,105.4) v1(96.2,104.64) v1(97.09,105.4) v1(97.09,104.64)
G_V_H: length 38.2
  TOP w0.762: v1(21.48,76.93) R125.2 C92.2 ; v1(26.8,75.13) 26.6,74.4 25.65,73.94 C79.2 25.69,74.09 25.08,75.21 23.87,75.19 C92.2 ; v1(31.49,68.47) PAD7.1 ; C92.2 D19.2 20.28,74.95 20.36,74.16 C105.1 C88.1 v1(20.78,71.19)
  BOTTOM w0.711: Q2.6 C3.2 R7.2
  BOTTOM w0.762: Q2.6 31.46,68.45 31.46,69.21 30.44,70.99 28.82,71.26 28.56,71.82 28.4,72.21 28.38,72.22 27.48,74.22 v1(26.8,75.13) 26.04,76.48 ; C103.2 R130.1 v1(33.31,76.53)
  vias: v1(32.68,69.54) v1(33.05,68.74) v1(33.37,69.87) v1(33.74,69.06)
G_W_H: length 43.8
  TOP w0.635: PAD9.1 103.53,35.37 v1(105.32,33.57)
  TOP w0.762: C118.1 110.59,24.09 108.98,24.11 C111.2 ; 107.44,27.04 108.18,28.44 R139.1 C117.2 110.02,29.13 ; 107.44,27.04 108.07,26.75 108.2,26.39 108.25,26.37 109.03,24.35 C111.2 ; 107.44,27.04 v1(107.4,27.08) ; C94.2 110.02,29.13 ; 110.02,29.13 110.96,29.47 112.7,28.66 113.51,28.38 113.91,27.28 C106.1 v1(114.65,26.28) ; R137.2 107.51,21.62 108.52,22.14 109.39,22.31 D25.2 C111.2
  BOTTOM w0.762: 107.37,27.02 107.31,27.07 107.08,29.18 104,30.74 103.67,31.87 104.43,33.47 105.39,33.47 Q3.6 108.18,32.12 108.18,32.13 108.81,31.83 109.27,32.01 C2.2 R6.2 ; 107.37,27.02 107.35,27.01 U11.3 ; 107.37,27.02 107.37,27.08 v1(107.4,27.08)
  vias: v1(102.07,35.65) v1(102.45,36.41) v1(102.86,35.32) v1(103.19,36.12)
IGND: length 92
  TOP w1.016: CN1.2 4.54,75.31 5.43,82.8 C35.2 9.36,88.9 CN2.2
  VCC02 w1.27: C35.2 9.84,88.69 CN2.2
  PWM04 w1.27: CN1.2 4.56,75.41 5.3,82.72 C35.2
  I_SAMPLING05 w1.27: CN2.2 9.44,89 C35.2
  BOTTOM w1.524: CN2.2 11.5,92.81 7.38,85.56 C35.2 5.3,82.16 4.63,78.53 4.78,74.87 6.06,70.61 CN1.2
IPH_U+: length 86.3
  GND03 w0.508: v1(76.75,84.43) 76.42,84.1 66.79,84.1 64.89,82.19 61.61,82.19 58.46,85.34 v1(58.38,85.34)
  PWM04 w0.508: v1(46.07,109.98) 46.32,109.72 46.32,100.71 47.21,99.82 47.23,99.82 47.23,94.37 49.12,89.76 52.66,86.5 53.82,85.34 v1(58.38,85.34)
  I_SAMPLING05 w0.508: J1.21 66.15,126.08 66.15,125.36 64.61,123.82 53.81,123.82 48.17,118.18 48.17,112.75 v1(46.07,109.98)
  BOTTOM w0.508: R42.2 C15.1 76.71,84.47 v1(76.75,84.43)
IPH_U-: length 353.4
  TOP w0.381: v1(83.87,120.51) 83.87,120.69 82.01,122.55 76.98,122.55 72.61,126.92 v1(72.61,128.9)
  VCC02 w0.381: v1(72.61,128.9) 72.61,129.51 71.69,130.43 68.47,130.43 68.09,130.05 J1.24
  GND03 w0.508: v1(58.38,84.32) 58.38,84.26 61.24,81.4 65.18,81.4 67.11,83.33 v1(76.75,83.33) ; v1(92.45,61.11) 88.23,64.51 87.95,67.38 92.3,76.08 95.21,78.99 v1(97.75,78.99)
  PWM04 w0.508: v1(58.38,84.32) 58.13,84.58 53.5,84.58 53.12,84.96 53.12,84.96 52.54,85.54 48.45,89.3 46.48,94.13 46.42,95.21 46.42,99.18 45.43,100.17 v1(45.43,107.44) ; v1(83.87,120.51) 84.3,120.09 85.44,120.09 86.48,121.13 108.07,121.13 115.28,113.79 115.28,99.37 97.88,81.97 97.88,79.12 v1(97.75,78.99)
  I_SAMPLING05 w0.381: 69.36,126.18 69.36,127.96 J1.26
  I_SAMPLING05 w0.508: J1.23 67.2,125.8 67.2,125.24 64.96,123.01 54.27,123.01 49,117.74 49,112.46 45.41,107.57 v1(45.43,107.44) ; v1(59.81,59.28) 59.82,58.92 59.39,58.26 59.33,58.24 59.28,58.15 58.68,57.98 58.12,58.28 57.89,59.07 58.46,60.42 58.94,61.57 58.94,70.68 54.37,79.7 39.04,86.63 36.16,93.09 35.98,96.2 37.49,99.22 46.26,106.37 50.13,111.88 50.13,117.43 54.79,122.09 66.25,122.09 69.36,125.2 69.36,126.18
  BOTTOM w0.508: v1(92.45,61.11) C16.2 94.45,64.36 95.19,65.98 94.96,66.68 94.15,67.18 ; CON2.1 39.77,14.93 R2.2 ; 63.67,54.61 61.74,53.82 61.36,54.07 59.98,56.87 C14.2 v1(59.81,59.28) ; 70.68,81.58 70.7,81.61 70.7,84.02 71.06,84.38 74.28,84.38 75.39,83.27 C15.2 76.11,83.37 76.71,83.37 v1(76.75,83.33)
  BOTTOM w0.762: C133.2 65.09,2.37 R35.1
  vias: v1(46.32,12.95) v1(46.32,11.68) v1(46.32,10.41) v1(47.59,12.95) v1(47.59,11.68) v1(47.59,10.41) v1(48.86,12.95) v1(48.86,11.68) v1(48.86,10.41) v1(50.13,12.95) v1(50.13,11.68) v1(50.13,10.41) v1(55.84,9.14) v1(55.84,7.87) v1(57.11,12.95) v1(57.11,11.68) v1(57.11,10.41) v1(57.11,9.14) v1(57.11,7.87) v1(58.38,12.95) v1(58.38,11.68) v1(58.38,10.41) v1(58.38,9.14) v1(58.38,7.87) v1(59.65,12.95) v1(59.65,11.68) v1(59.65,10.41) v1(59.65,9.14) v1(59.65,7.87) v1(60.92,85.34) v1(60.92,12.95) v1(60.92,11.68) v1(60.92,10.41) v1(61.05,84.58) v1(61.18,86.1) v1(61.43,83.94) v1(61.81,86.61) v1(62.07,83.56) v1(62.32,57.78) v1(62.7,57.02) v1(62.83,83.43) v1(63.08,58.16) v1(63.08,56.26) v1(63.34,86.74) v1(63.46,57.4) v1(63.46,55.49) v1(63.59,83.69) v1(63.72,47.62) v1(63.85,58.54) v1(63.85,56.64) v1(63.85,54.73) v1(63.97,86.36) v1(64.1,84.2) v1(64.1,48.38) v1(64.23,55.88) v1(64.23,53.97) v1(64.35,85.59) v1(64.48,84.83) v1(64.61,55.11) v1(64.61,53.21) v1(64.73,48.89) v1(64.86,45.59) v1(64.99,54.35) v1(64.99,52.45) v1(65.37,55.49) v1(65.37,53.59) v1(65.37,51.68) v1(65.62,49.02) v1(65.62,45.59) v1(65.75,52.83) v1(65.75,50.92) v1(66.13,52.07) v1(66.39,48.64) v1(66.39,45.84) v1(66.51,51.3) v1(66.89,48) v1(66.89,46.48) v1(67.15,47.24) v1(67.27,51.81) v1(67.6,82.37) v1(67.6,81.76) v1(68.49,82.37) v1(68.49,81.76) v1(69.38,82.37) v1(69.38,81.76) v1(70.27,82.37) v1(70.27,81.76) v1(71.16,82.37) v1(71.16,81.76) v1(72.05,82.37) v1(72.05,81.76) v1(72.94,82.37) v1(72.94,81.76) v1(73.83,82.37) v1(73.83,81.76) v1(74.72,82.37) v1(74.72,81.76) v1(89.75,66.29) v1(90.13,67.05) v1(90.52,67.81) v1(90.9,68.58) v1(90.9,64.77) v1(91.28,69.34) v1(91.28,65.53) v1(91.66,70.1) v1(91.66,66.29) v1(91.66,64.38) v1(92.04,70.86) v1(92.04,67.05) v1(92.04,65.15) v1(92.42,71.62) v1(92.42,67.81) v1(92.42,65.91) v1(92.8,72.39) v1(92.8,68.58) v1(92.8,66.67) v1(93.18,69.34) v1(93.18,67.43) v1(93.56,72) v1(93.56,70.1) v1(93.56,68.19) v1(93.94,70.86) v1(93.94,68.96) v1(94.33,71.62) v1(94.33,69.72) v1(94.71,70.48) v1(95.09,71.24) v1(98.14,72.77) v1(98.26,72) v1(98.39,73.53) v1(98.64,71.37) v1(99.02,74.16) v1(99.28,70.99) v1(99.91,74.42) v1(100.29,70.86) v1(100.68,74.16) v1(101.06,71.37) v1(101.31,73.66) v1(101.56,72.89) v1(101.56,72)
